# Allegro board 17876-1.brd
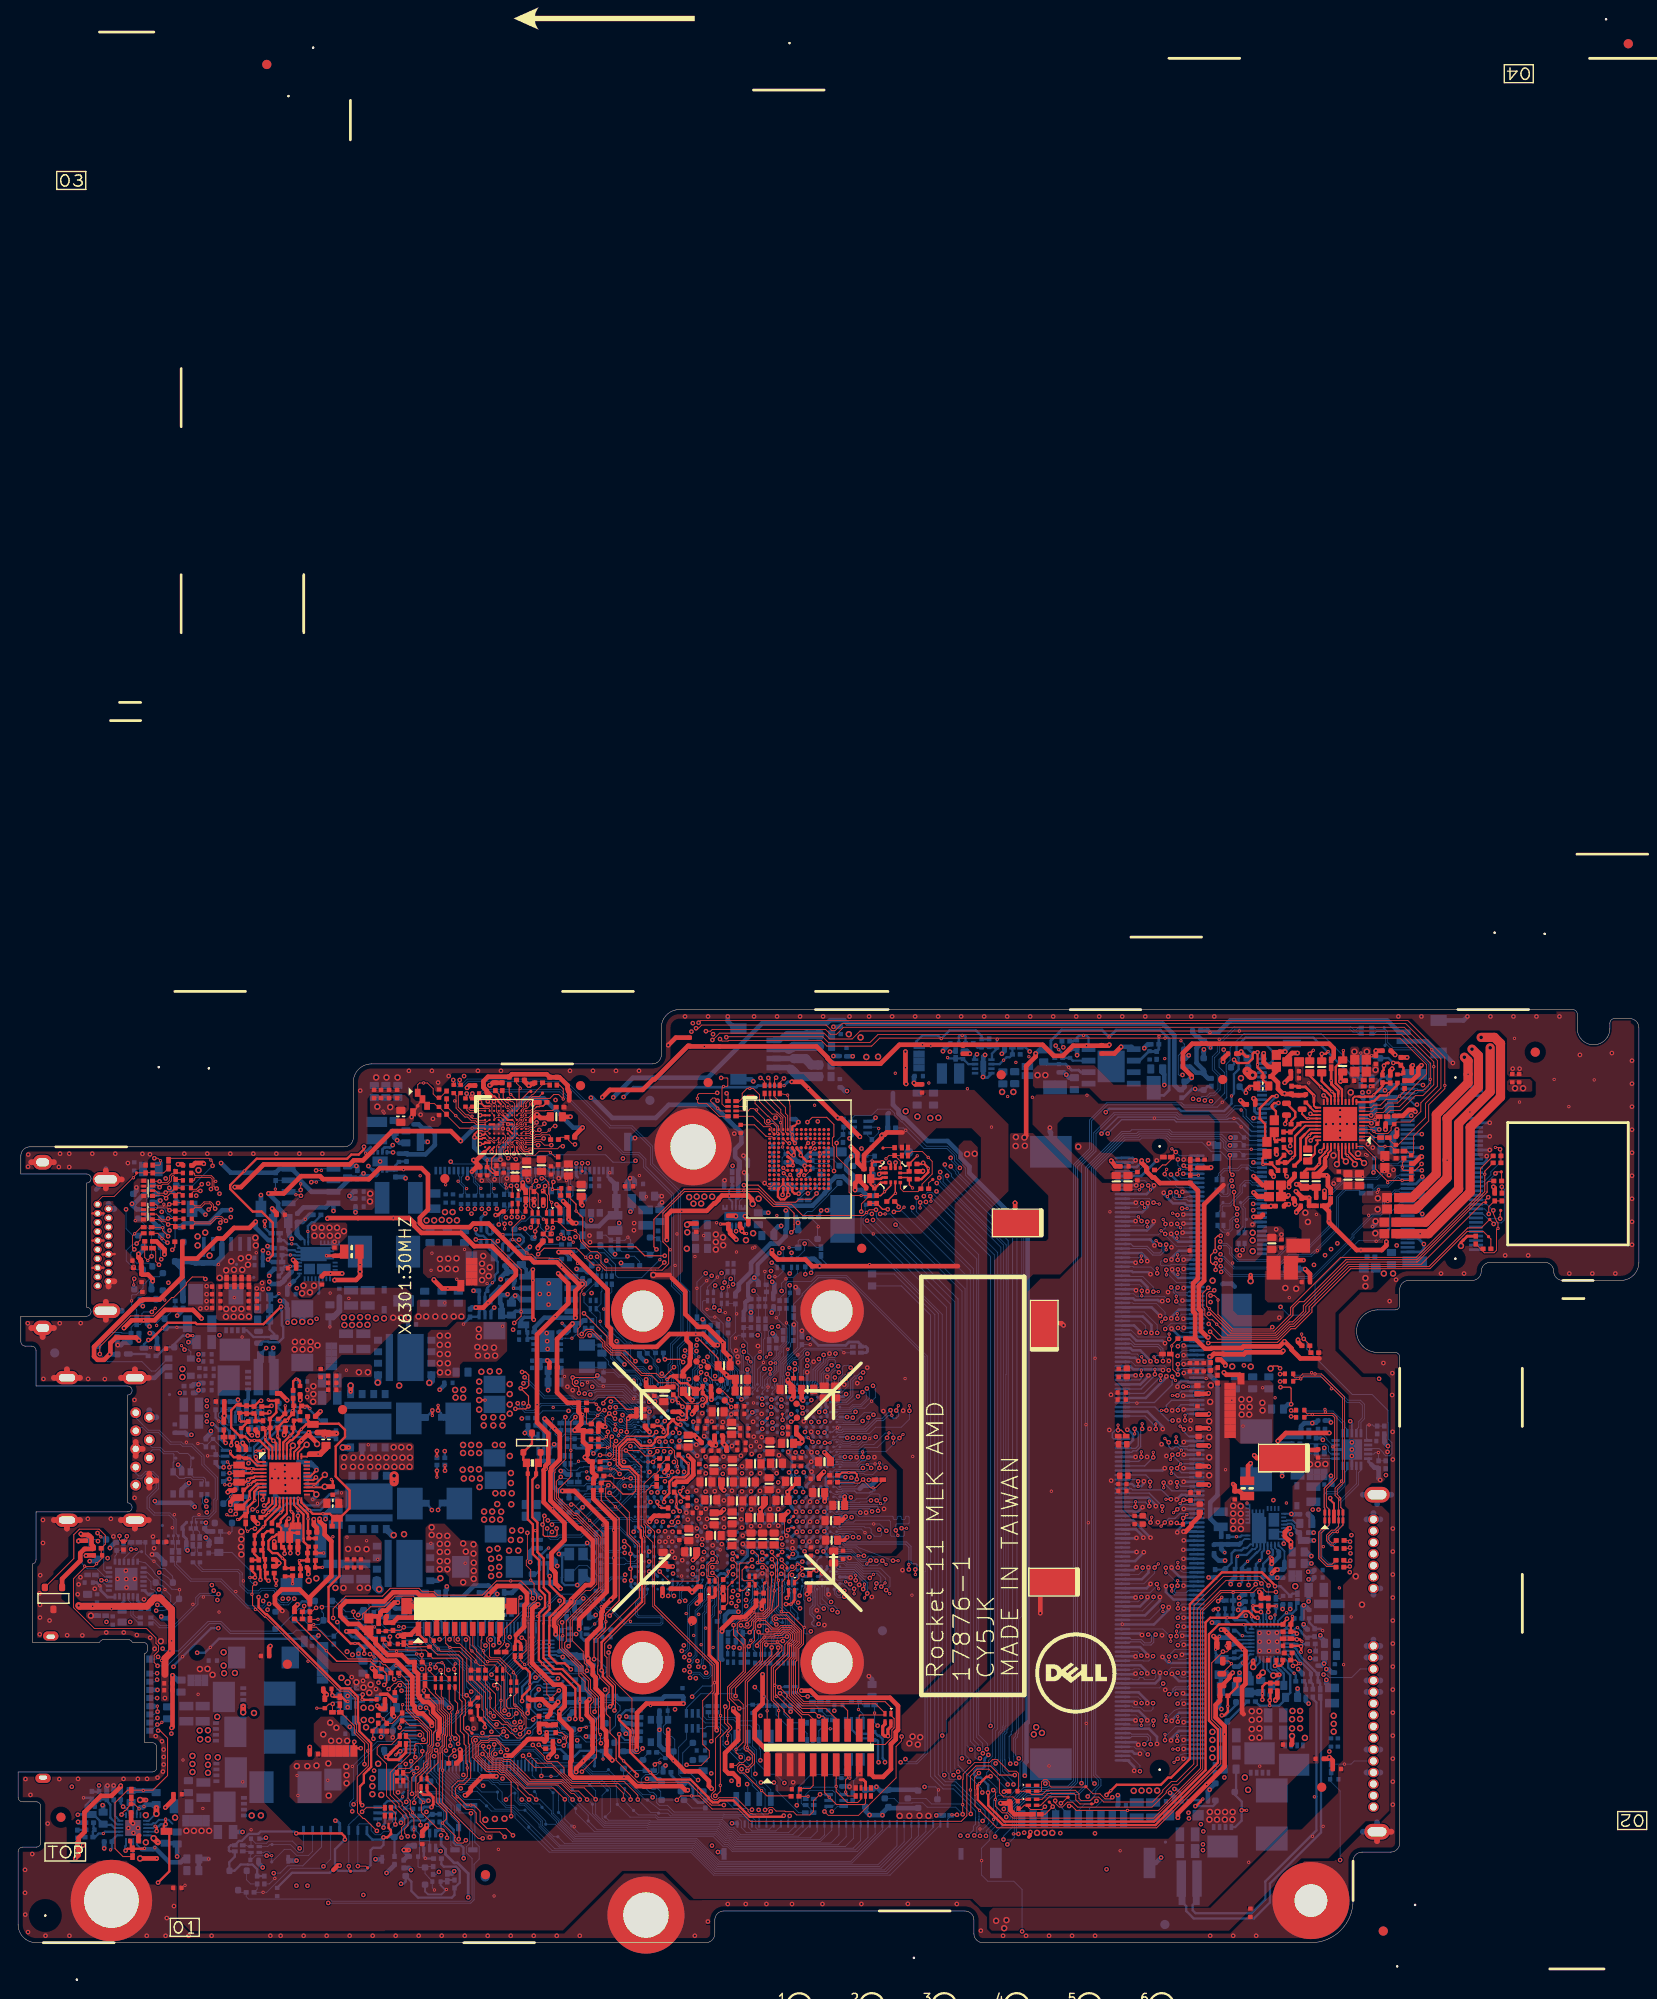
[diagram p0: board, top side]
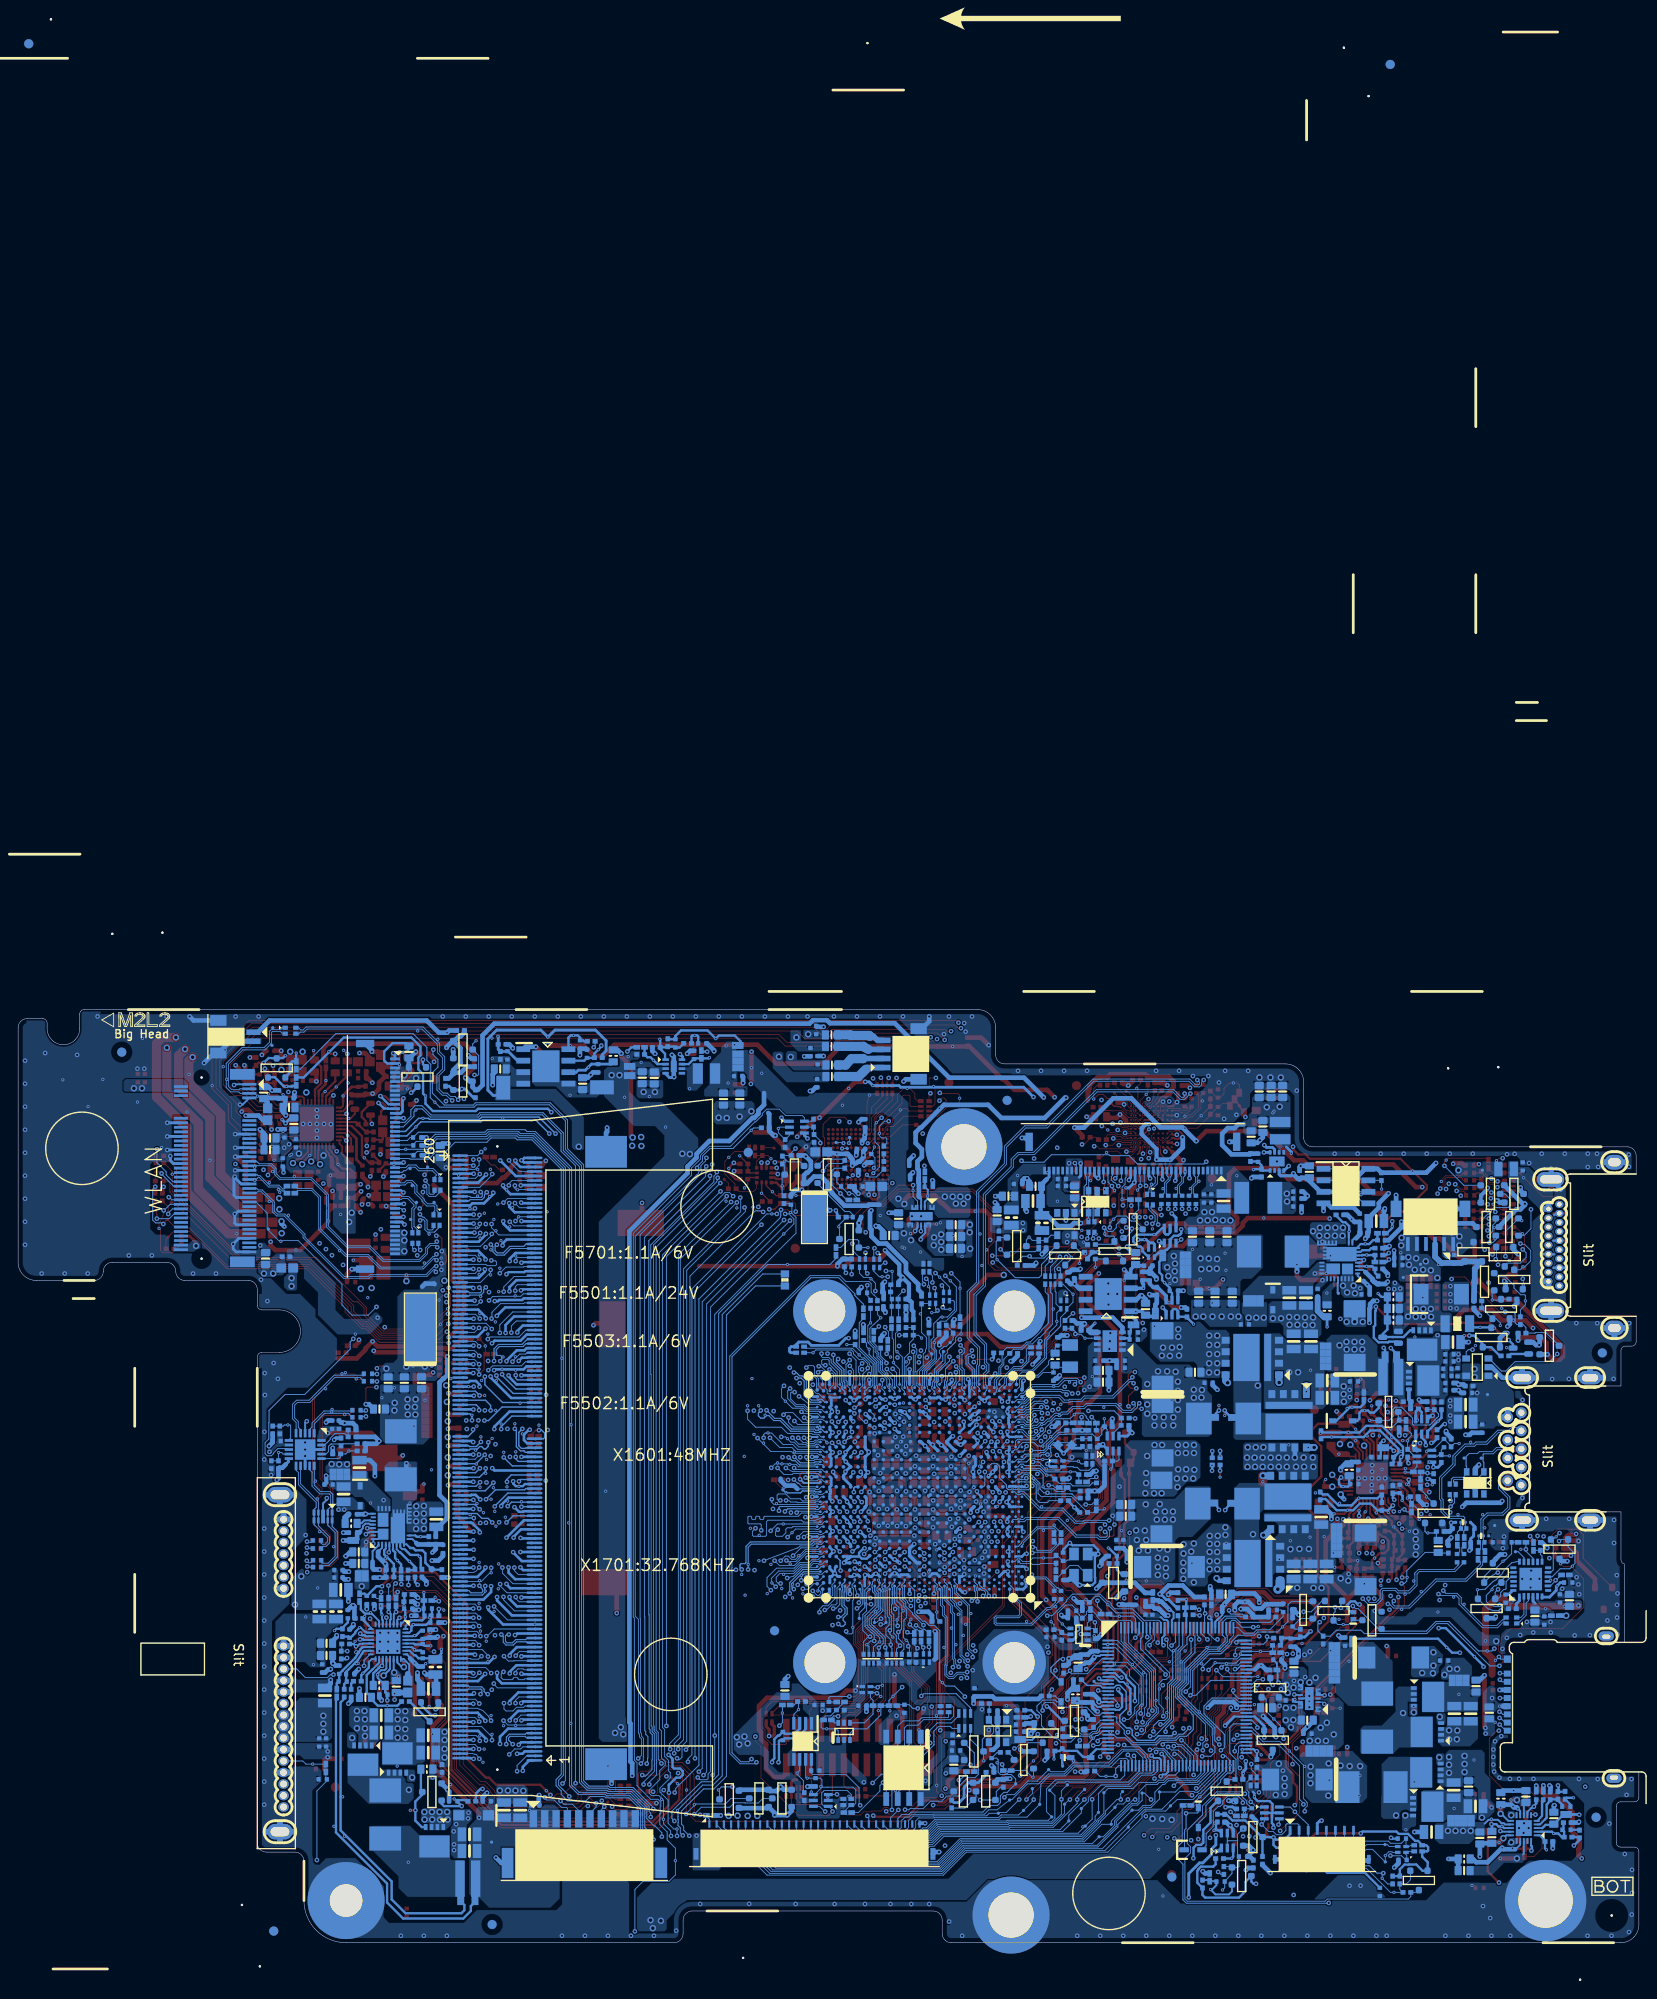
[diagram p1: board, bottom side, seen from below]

Outline 178.9 x 103 mm; copper layers: TOP, L2VCC, L3, L4, L5GND, BOTTOM. Coordinates in mm from the lower left corner of the outline.
Outline path: 0,18.85 0,16.05 arc(0.15,15.7) 0.5,15.55 2,15.55 arc(2.35,15.4) 2.5,15.05 2.5,11.05 arc(2.35,10.7) 2,10.55 0.5,10.55 arc(0.15,10.4) 0,10.05 0,2 arc(0.59,0.59) 2,0 75.9,0 arc(76.61,0.29) 76.9,1 76.9,2.5 arc(77.19,3.21) 77.9,3.5 104.5,3.5 arc(105.21,3.21) 105.5,2.5 105.5,1 arc(105.79,0.29) 106.5,0 142.7,0 arc(145.99,1.36) 147.35,4.65 147.35,9 arc(147.64,9.71) 148.35,10 151.5,10 arc(152.21,10.29) 152.5,11 152.5,64.65 arc(152.35,65) 152,65.15 150.09,65.15 arc(147.74,67.5) 150.09,69.85 152,69.85 arc(152.35,70) 152.5,70.35 152.5,72.1 arc(152.79,72.81) 153.5,73.1 160.5,73.1 arc(161.21,73.39) 161.5,74.1 arc(161.79,74.81) 162.5,75.1 168.5,75.1 arc(169.21,74.81) 169.5,74.1 arc(169.79,73.39) 170.5,73.1 176.9,73.1 arc(178.31,73.69) 178.9,75.1 178.9,101 arc(178.61,101.71) 177.9,102 176.2,102 arc(175.85,101.85) 175.7,101.5 175.7,100.9 arc(173.9,99.1) 172.1,100.9 172.1,102.5 arc(171.95,102.85) 171.6,103 73,103 arc(71.59,102.41) 71,101 71,98 arc(70.71,97.29) 70,97 39,97 arc(37.59,96.41) 37,95 37,88.85 arc(36.71,88.14) 36,87.85 1.3,87.85 arc(0.59,87.56) 0.3,86.85 0.3,84.85 7.55,84.85 arc(8.05,84.35) 7.55,83.85 7.55,70.15 arc(8.05,69.65) 7.55,69.15 0.3,69.15 0.3,66.35 arc(0.45,66) 0.8,65.85 1.48,65.85 arc(1.83,65.7) 1.98,65.35 1.98,61.45 12.08,61.45 arc(12.58,60.95) 12.08,60.45 12.08,48.55 arc(12.58,48.05) 12.08,47.55 1.98,47.55 1.98,42.29 arc(1.87,41.98) 1.6,41.8 1.6,33.15 8.99,33.15 arc(9.18,33.37) 9.45,33.46 12.15,33.46 arc(12.42,33.37) 12.61,33.15 13.8,33.15 arc(14.15,33.01) 14.3,32.66 14.3,32.38 arc(14.2,32.08) 13.95,31.9 13.95,22.07 14.8,22.07 arc(15.15,21.93) 15.3,21.58 15.3,19.34 arc(15.15,18.99) 14.8,18.85 0,18.85

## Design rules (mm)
constraint set DEFAULT: min track width 0.127
net group 3V_5V_10MIL: nets PWR_3D3V_FB PWR_5V_FB
net group APU_SVC: nets APU_SVC SVID_CLK_CPU
net group APU_SVD: nets APU_SVD SVID_DATA_CPU
net group APU_SVT: nets APU_SVT SVID_ALERT#_CPU
net group AUDIO_DIGITAL_50_MW_TP: nets HDA_CODEC_SDIN1_R HDA_CODEC_SDIN2_R
net group BT_USB20_CON_N5: nets BT_USB20_CON_N5 BT_USB20_N5
net group BT_USB20_CON_P5: nets BT_USB20_CON_P5 BT_USB20_P5
net group CARD1_USB20_CON_N2: nets CARD1_USB20_CON_N2 CARD1_USB20_N2
net group CCD_USB20_CON_N0: nets CCD_USB20_CON_N0 CCD_USB20_N0
net group CORE_SENSE-DIFF1: nets VCCCORE_SENSE VSSCORE_SENSE
net group DDR4_CHA_CMD_55OHM: nets M_A_EVENT# M_A_EVENT#_APU
net group EDP_AUX_CON_N: nets EDP_AUX_CON_N EDP_AUX_CPU_N
net group EDP_AUX_CON_P: nets EDP_AUX_CON_P EDP_AUX_CPU_P
net group EDP_TX_CON_N0: nets EDP_TX_CON_N0 EDP_TX_CPU_N0
net group EDP_TX_CON_N1: nets EDP_TX_CON_N1 EDP_TX_CPU_N1
net group EDP_TX_CON_P0: nets EDP_TX_CON_P0 EDP_TX_CPU_P0
net group EDP_TX_CON_P1: nets EDP_TX_CON_P1 EDP_TX_CPU_P1
net group EMMC_SATA_RX_N1: nets EMMC_SATA_RX_N1 EMMC_SATA_RX_N1_C
net group EMMC_SATA_RX_P1: nets EMMC_SATA_RX_P1 EMMC_SATA_RX_P1_C
net group EMMC_SATA_TX_N1: nets EMMC_SATA_TX_N1 EMMC_SATA_TX_N1_C
net group EMMC_SATA_TX_P1: nets EMMC_SATA_TX_P1 EMMC_SATA_TX_P1_C
net group FAN_TACH: nets FAN_TACH1 FAN_TACH1_C
net group HDA_BITCLK_CODEC: nets HDA_BITCLK_CODEC HDA_BITCLK_CODEC_R
net group HDD_SATA_RX_CON_N0: nets HDD_SATA_RX_RE_N1 SATA3_PRX_DTX_N0_L
net group HDD_SATA_RX_CON_P0: nets HDD_SATA_RX_RE_P1 SATA3_PRX_DTX_P0_L
net group HDMI_DDI_TX_CON_N0: nets HDMI_DDI_TX_CON_N0 HDMI_DDI_TX_N0
net group HDMI_DDI_TX_CON_N3: nets HDMI_DDI_TX_CON_N3 HDMI_DDI_TX_N3
net group HDMI_DDI_TX_CON_P0: nets HDMI_DDI_TX_CON_P0 HDMI_DDI_TX_P0
net group HDMI_DDI_TX_CON_P3: nets HDMI_DDI_TX_CON_P3 HDMI_DDI_TX_P3
net group I2C_TP: nets SENSOR_I2C_SCL SENSOR_I2C_SDA
net group M_A_CLK-DIFF0: nets M_A_CLK0 M_A_CLK#0
net group M_A_CLK-DIFF1: nets M_A_CLK1 M_A_CLK#1
net group M_A_DQS-DIFF0: nets M_A_DQS_DN0 M_A_DQS_DP0
net group M_A_DQS-DIFF1: nets M_A_DQS_DN1 M_A_DQS_DP1
net group M_A_DQS-DIFF2: nets M_A_DQS_DN2 M_A_DQS_DP2
net group M_A_DQS-DIFF3: nets M_A_DQS_DN3 M_A_DQS_DP3
net group M_A_DQS-DIFF4: nets M_A_DQS_DN4 M_A_DQS_DP4
net group M_A_DQS-DIFF5: nets M_A_DQS_DN5 M_A_DQS_DP5
net group M_A_DQS-DIFF6: nets M_A_DQS_DN6 M_A_DQS_DP6
net group M_A_DQS-DIFF7: nets M_A_DQS_DN7 M_A_DQS_DP7
net group NB_SENSE-DIFF1: nets VDDNB_SENSE VSSNB_SENSE
net group OTHER_6: nets RSTN S5_ENABLE
net group POWER_12_TP: nets CARD_AV18 CARD_RREF
net group POWER_15M: nets PWR_0D775V PWR_0D775V_VREF
net group POWER_20_TP: nets AD+_G_2 Q2506_S
net group POWER_20M_10M: nets CPVDD PWR_CHG_CMSRC
net group POWER_40M_25M: nets PWR_CORE_LG1 PWR_VDDNB_LG
net group POWER_100: nets EMMC_VCC PWR_VDDQ_VTTREF
net group POWER_VDDQ_280M: nets PWR_VDDQ_VCC VTT_CT_0.95V
net group PSID_4M: nets PS_ID PSID_EC
net group PWR_VDDNB_CORE_5M: nets PWR_CORE_HG1 PWR_VDDNB_HG
net group SD_MMC_CLK/MS_DATA2: nets SD_MMC_CLK/MS_DATA2 SP5
net group SENSE_CHG_PG-DIFF1: nets PG_1 PG_2
net group SENSE_CHG_SRPN-DIFF1: nets PWR_CHG_SRN PWR_CHG_SRP
net group SIGNAL_V_F_50_OHM: nets BP_D BP_G
net group T8: nets VD_IN1 VD_IN1_C
net group THERM_10MIL: nets VD1_EN# VD_OUT1#
net group THERMAL-DIFF: nets P2800_DXN P2800_DXP
net group USB1_USB30_TX_CMC_N2: nets USB1_USB30_TX_CMC_N2 USB1_USB30_TX_N2
net group USB1_USB30_TX_CMC_P2: nets USB1_USB30_TX_CMC_P2 USB1_USB30_TX_P2
net group USB3_RX_CON-DIFF1: nets USB1_USB30_RX_CON_N2 USB1_USB30_RX_CON_P2
net group USB3_RX_CPU-DIFF1: nets USB1_USB30_RX_N2 USB1_USB30_RX_P2
net group USB3_TX_CON-DIFF1: nets USB1_USB30_TX_CON_N2 USB1_USB30_TX_CON_P2
net group WLAN_CLK_CPU_N3: nets WLAN_CLK_CPU_N3 WLAN_CLK_CPU_N3_R
net group WLAN_CLK_CPU_P3: nets WLAN_CLK_CPU_P3 WLAN_CLK_CPU_P3_R
net group WLAN_PCIE_TX_CON_N3: nets WLAN_PCIE_TX_CON_N3 WLAN_PCIE_TX_N3
net group WLAN_PCIE_TX_CON_P3: nets WLAN_PCIE_TX_CON_P3 WLAN_PCIE_TX_P3
net group WLANTX_N3: nets WLAN_PCIE_RX_N3 WLANTX_N3
net group WLANTX_P3: nets WLAN_PCIE_RX_P3 WLANTX_P3
net group XTL_48M_TP: nets 48M_X2 R1930.R
net group 3V_5V_10MIL_TP: nets PWR_5V_FB_A
net group 3V_5V_20MIL: nets PWR_3D3V_BOOT PWR_3D3V_BOOT_A PWR_5V_BOOT PWR_5V_BOOT_A
net group APU_SPI_CLK: nets APU_SPI_CLK SPI_CLK_KBC SPI_CLK_ROM
net group APU_SPI_CS1#: nets SPI_CS_ROM_N0
net group APU_SPI_HOLD#: nets SPI_HOLD_CPU
net group APU_SPI_SI_R: nets APU_SPI_SI_R SPI_SI_KBC SPI_SI_ROM
net group APU_SPI_SO_R: nets SPI_SO_CPU
net group APU_SPI_WP#: nets SPI_WP_CPU
net group BKLT_EDP-MW: nets BKLT_CTRL EC_BRIGHTNESS L_BKLT_CTRL L_BKLT_CTRL_B L_BKLT_CTRL_CPU LCD_BRIGHTNESS LVDS_VDD_EN LVDS_VDD_EN_B LVDS_VDD_EN_CPU LVDS_VDD_EN_R
net group CCD_USB20_CON_P0: nets CCD_USB20_CON_P0
net group CLK_FST_SPI-MW: nets SPI_SCK
net group CPU_SIDE-MW: nets AD_IA DBC_EN DBC_EN_R ECSMI#_KBC EDP_HPD_CPU FALL_INT2 FFS_INT2 FFS_INT2_Q FFS_INT2_Q_R HDMI_DET_CPU HDMI_HPD_B HDMI_HPD_E HDMI_HPD_G HPD_HDMI_CON INT_TP# INT_TP#_CONN PLT_RST# PM_PWRBTN# PROCHOT#_EC PROJECT_ID1 RSMRST#_KBC RTC_CLK WLAN_CLKREQ_CPU_N3
net group CPU_SIDE_PROCHOT: nets H_PROCHOT#
net group DDR4_CHA_CMD-MW: nets DDR4_A_DRAMRST# M_A_A0 M_A_A1 M_A_A2 M_A_A3 M_A_A4 M_A_A5 M_A_A6 M_A_A7 M_A_A8 M_A_A9 M_A_A10 M_A_A11 M_A_A12 M_A_A13 M_A_ACT# M_A_ALERT_N M_A_BA0 M_A_BA1 M_A_BG0 M_A_BG1 M_A_CAS# M_A_PARITY M_A_RAS# M_A_WE# M_VREFDQ
net group DDR4_CHA_CTRL-MW: nets M_A_CKE0 M_A_CKE1 M_A_CS#0 M_A_CS#1 M_A_ODT0 M_A_ODT1
net group DDR4_CHA_DATA-MW: nets M_A_DM0 M_A_DM1 M_A_DM2 M_A_DM3 M_A_DM5 M_A_DM6 M_A_DM7 M_A_DQ0 M_A_DQ1 M_A_DQ2 M_A_DQ3 M_A_DQ4 M_A_DQ6 M_A_DQ7 M_A_DQ8 M_A_DQ9 M_A_DQ10 M_A_DQ11 M_A_DQ12 M_A_DQ13 M_A_DQ14 M_A_DQ15 M_A_DQ16 M_A_DQ17 M_A_DQ18 M_A_DQ19 M_A_DQ20 M_A_DQ21 M_A_DQ22 M_A_DQ23 M_A_DQ24 M_A_DQ25 M_A_DQ26 M_A_DQ28 M_A_DQ29 M_A_DQ34 M_A_DQ35 M_A_DQ38 M_A_DQ39 M_A_DQ40 M_A_DQ41 M_A_DQ42 M_A_DQ43 M_A_DQ44 M_A_DQ45 M_A_DQ46 M_A_DQ47 M_A_DQ48 M_A_DQ49 M_A_DQ50 M_A_DQ51 M_A_DQ52 M_A_DQ53 M_A_DQ54 M_A_DQ55 M_A_DQ56 M_A_DQ57 M_A_DQ58 M_A_DQ59 M_A_DQ60 M_A_DQ61 M_A_DQ62 M_A_DQ63
net group DDR4_CHA_DATA_10M: nets M_A_DM4 M_A_DQ27 M_A_DQ30 M_A_DQ31 M_A_DQ32 M_A_DQ33 M_A_DQ36 M_A_DQ37
net group DDR4_CHA_DATA_MW_TP: nets M_A_DQ5
net group EMMC_S10: nets EMMC_E9 EMMC_E10 EMMC_F10 EMMC_K10 EMMC_RESET# EMMC_VCC1N EMMC_VCC2N
net group EMMC_S10_TP: nets EMMC_VDDI
net group GND_20: nets MIC_GND
net group GND_100: nets AUD_AGND
net group HDA_CODEC_SDIN0_R: nets HDA_SDIN0_CPU
net group HDA_CODEC_SDOUT_R: nets HDA_SDOUT_CODEC
net group HDA_CODEC_SYNC_R: nets HDA_SYNC_CODEC
net group HDMI_DDI_TX_CON_N1: nets HDMI_DDI_TX_N1
net group HDMI_DDI_TX_CON_N2: nets HDMI_DDI_TX_N2
net group HDMI_DDI_TX_CON_P1: nets HDMI_DDI_TX_P1
net group HDMI_DDI_TX_CON_P2: nets HDMI_DDI_TX_P2
net group I2C: nets I2C1_1V8_CLK I2C1_1V8_DATA SENSOR_I2C_SCL_R SENSOR_I2C_SDA_R TP_CLK TP_DAT TP_I2C_CLK TP_I2C_DATA
net group KB: nets KCOL0 KCOL1 KCOL2 KCOL3 KCOL4 KCOL5 KCOL6 KCOL7 KCOL8 KCOL9 KCOL10 KCOL11 KCOL12 KCOL13 KCOL14 KCOL15 KCOL16 KROW0 KROW1 KROW2 KROW3 KROW4 KROW5 KROW6 KROW7
net group LPC-MW: nets APU_LPC_PD# APU_LPC_PME# APU_LPC_SMI# INT_SERIRQ
net group M_ZVDDIO: nets M_ZVDDIO P_ZVDDP P_ZVSS SATA_ZVSS
net group OTHER_4: nets 1D8V_AUX_EN 1D8V_S0_EN 1D8V_S0_EN_R 1D8V_SPI_EN# 3V_5V_EN 3V_S0_EN 5V_DDC_HDMI1 5V_DDC_HDMI2 AC_PRES_KBC AC_PRES_R AGPIO3 AGPIO11 AGPIO92 AGPIO130 ALERT# APU_ALERT# APU_DBRDY APU_DBREQ# APU_DEVSLP1 APU_FANIN APU_FANOUT APU_LDRQ0# APU_PWRBTN#_R APU_PWROK APU_PWROK_HDT APU_RSMRST# APU_RSMRST#_R APU_RST# APU_RST#_R APU_RST_L_BUF APU_S0A3_IND APU_SIC APU_SID APU_SLP_S3# APU_SLP_S5# APU_TCK APU_TDI APU_TDO APU_TEST0 APU_TEST1 APU_TEST2 APU_TEST6 APU_TEST9 APU_TEST10 APU_TEST14_BP1 APU_TEST15_BP3 APU_TEST16_BP5 APU_TEST17_BP7 APU_TEST18_HDT20 APU_TEST19_HDT18 APU_TEST28_H APU_TEST28_L APU_TEST31 APU_TEST36 APU_TEST41 APU_THERMDA APU_THERMDC APU_TMS APU_TRST# APU_TRST#_R APU_VSS_SENSE_A BAT_IN# BLON_OUT BLUETOOTH_EN BLUETOOTH_EN_R CAP_LED CAP_LED# CAP_LED_R# CLK_REQG CR_GPIO0 DBRDY1 DBRDY2 DBRDY3 DP_2K_ZVSS DP_150_ZVSS DP_HPD0_C DVSS E51_RX1 E51_RX2 E51_TX1 E51_TXD EC_MUTE# ECRST# ECSCI#_KBC EDP_BLON EGPIO95 EGPIO96 EGPIO99 EGPIO100 FAN_PWM1_C GPIO1 GPIO2 GPIO3 GPIO67 GROUPB_PWRGD H_A20GATE HALL_KB_DIS# HDD_DEVSLP HDD_DEW1 HDD_DEW2 HDMI_IN# HVBEN_L INT_SERIRQ_OE INT_TP#_R KB_LOOP KBC_BEEP KBC_ON#_GATE KBC_ON#_GATE_L KBC_PECI KBC_PWRBTN# KBRST# LCD_TST LCD_TST_EN LCD_TST_KBC LID_CLOSE# LVDS_VDD_EN_KBC MODEL_ID MODEL_ID_AD NC#7 PBAT_PRES1# PCB_VER_AD PCIE_RST#_C PDB_R PLTRST#_CPU_D PQ3802_1 PQ4405_2 PQ4405_3 PQ4405_5 PQ4405_6 PQ4408_C PQ4408_E PQ4415_C PSID_DISABLE#_R_C PSL_IN2# PSL_OUT# PURE_HW_SHUTDOWN# PWR_3D3V_EN Q1702_2 Q2406_D Q2406_G RTC_DET# RUNPWROK_D S5_MUX_APU SATA3_DE1_HDD SATA3_DE2_HDD SD_CD# SD_WP#/MS_DATA1_C SENSOR_KB_DIS SER_RXD SER_TXD SVID_PWRGD SVID_PWRGD_R SYS_PRES1# SYS_PWRGD SYS_PWRGD_G SYS_PWRGD_R SYS_RESET# T_CRIT# THERM_SYS_SHDN# TOUCH_PANEL_EN TP_DISABLE# TP_DISABLE#_R TP_ON# TP_ON#_GATE UART_RX UART_TX USB2_PWR_EN# USB3_PWR_EN# USB_OC#0 USB_OC#1 VOL_DOWN# VOL_UP# WAKE_L WIFI_RF_EN WIFI_RF_EN_R
net group OTHER_4_TP: nets 1D8V_S0_EN_D APU_KBRST# BLON_OUT_C CAP_LED_Q GPIO0 GPIO4 GPIO5 GROUPB_PWRGD_R LCD_TST_C PSL_IN1# Q5102_G RTCRST_ON SATA3_EQ1_HDD SATA3_EQ2_HDD SD_CD#_CARD
net group OTHER_5: nets ACLIM TOUCH_PANEL_INTR# TPNL_INT
net group OTHER_6_TP: nets SD1_REXT
net group OTHER_12: nets LDO1_CAP LDO2_CAP LDO3_CAP V3D3_STB
net group OTHER_12_TP: nets CPVEE
net group P27_AUDIO_ANALOG: nets AUD_HP1_JACK_R AUD_HP1_JACK_R1 AUD_PC_BEEP AUD_PC_BEEP_C AUD_PORTA_L_R_B AUD_PORTA_R_R_B AUD_SENSE AUD_SENSE_A CBN HDA_SPKR_R JACK_PLUG KBC_BEEP_R LINE1-L_C LINE1-L_R LINE1_L LINE1_R LINE1_VREFO SPKR
net group P27_AUDIO_ANALOG_TP: nets AUD_HP1_JACK_L AUD_HP1_JACK_L1 AUD_VREF CBP LINE1_VREFO_D1 LINE1_VREFO_D2
net group POWER_4M: nets DM1_SA0 DM1_SA1 DM1_SA2
net group POWER_8: nets Q6204_S
net group POWER_10: nets 3D3V_GSEN2 3V5V_CT2 5V_AUX_S5 ACOK_IN I_BATT MIC_CAP PD4410_2 PQ4209_D PWR_1D8V_FB PWR_CHG_ACDET PWR_CHG_ACN PWR_CHG_ACOK PWR_CHG_ACP PWR_CHG_REGN PWR_CHG_SCL PWR_CHG_SDA PWR_CPU_ISEN1 Q6205_D Q6206_D RTC_1D5V_PWR RTC_1D5V_S5 SATA_ZVDD_095 USB_SS_ZVDD_095 USB_SS_ZVSS USB_ZVSS VDD VDDIO_AUDIO
net group POWER_10_TP: nets 3V5V_CT1
net group POWER_10_VIA: nets DC_IN_D
net group POWER_10_VIA_TP: nets AD+_G_1
net group POWER_10M_10M: nets 1D8V_S5_PWRGD 5V_S0_EN AC_DIS_R CCLIM PR_2 PWR_1D0V_FB PWR_CHG_AD_OFF_R VCORE_PWRGD
net group POWER_10M_POWER: nets 0D95V_S0_EN 0D95V_S5_EN 0D95V_S5_PWRGD 3V_5V_PWRGD 3V_5V_PWRGD_R AD+_R AD_OFF_L AD_OFF_R PWR_0D95V_CS PWR_0D95V_EN PWR_0D95V_FB PWR_0D95V_PG PWR_0D775V_EN PWR_0D775V_EN_R PWR_1D8V_EN PWR_1D8V_FB_R1 PWR_1D8V_FB_R2 PWR_1D8V_PG PWR_2D5V_PWRGD PWR_3D3V_FB_A PWR_3D3V_FB_B PWR_5V_EN PWR_5V_VO PWR_5V_VREG PWR_CHG_AD_OFF PWR_CHG_AMON PWR_CHG_ASGATE PWR_CHG_BATGONE PWR_CHG_BMON PWR_CHG_COMP PWR_CHG_FSET PWR_CHG_NTC PWR_CHG_SRN_R PWR_CHG_SRP_R PWR_CORE_COMP PWR_CORE_COMP_A PWR_CORE_COMP_B PWR_CORE_EN PWR_CORE_FB_A PWR_CORE_FB_R PWR_CORE_IMON PWR_CORE_ISEN1_N PWR_CORE_ISEN1_P PWR_CORE_ISEN_N PWR_CORE_ISEN_P PWR_CORE_ISUMN PWR_CORE_ISUMP PWR_CORE_NTC PWR_CORE_NTC_A_R PWR_CORE_PGOOD PWR_CORE_SVC PWR_CORE_SVD PWR_CORE_SVT PWR_CORE_VDD PWR_CORE_VDDIO PWR_CORE_VSEN1_N PWR_CORE_VSEN1_P PWR_OPCN PWR_OPCP PWR_VBAT PWR_VDDNB_COMP PWR_VDDNB_FB PWR_VDDNB_FB_A PWR_VDDNB_FB_B PWR_VDDNB_FB_C PWR_VDDNB_ISEN1_N PWR_VDDNB_ISEN1_N_A PWR_VDDNB_ISEN1_P PWR_VDDNB_ISEN1_P_A PWR_VDDNB_ISUMN PWR_VDDNB_ISUMN_A PWR_VDDNB_NTC PWR_VDDNB_NTC_A PWR_VDDNB_PG PWR_VDDNB_VSEN PWR_VDDNBE_IMON PWR_VDDQ_CS PWR_VDDQ_EN PWR_VDDQ_FB PWR_VDDQ_TON PWR_VPP_EN1 PWR_VTT_EN VDDQ_PWRGD
net group POWER_10M_POWER_TP: nets 0D775V_S5 PWR_0D95V_TON PWR_3D3V_CS PWR_3D3V_VREG PWR_5V_CS PWR_CHG_DCIN PWR_CHG_DCIN_R PWR_CHG_NTC_1 PWR_CHG_PROG PWR_CORE_VR_HOT#
net group POWER_12: nets PWR_VPP_FB PWR_VPP_VCNTL SDREG
net group POWER_15M_TP: nets PWR_0D775V_VIN
net group POWER_20: nets 1D8V_DVDD-IO +3V_1D8V_AVDD +RTC_PWR DDR_VREF_S3 EC_AVCC EC_VCC1V8 KBC_VCORF PD4403_A PD4403_K PWR_0D95V_SNUB PWR_CHG_BATDRV PWR_VDDQ_SNUB Q6203_S RTC_AUX_S5 RTC_DET#_G TPAN_VDD VBKUP VTT_CT_1.8V
net group POWER_25M: nets VDDCR_FCH_EN
net group POWER_25M_20M: nets PWR_0D95V_BOOT_A PWR_VDDNB_BOOT PWR_VDDNB_BOOT_A
net group POWER_25M_20M_TP: nets PWR_CHG_BTST PWR_CHG_BTST1 PWR_VDDQ_BOOT PWR_VDDQ_BOOT_A
net group POWER_40: nets SD1_POWER
net group POWER_40M_10M: nets PWR_0D95V_VCC PWR_0D95V_VDDQ PWR_0D95V_VLDOIN PWR_0D95V_VTTREF
net group POWER_240M_10M: nets PWR_VDDQ_VDDQ
net group POWER_VDDQ_280M_TP: nets PWR_VDDQ_LVOIN
net group PSID_25MIL: nets PS_ID_R
net group SD_DATA_CMD: nets SD_MMC_CMM/MS_DATA3 SD_MMC_DAT1 SD_MMC_DATA0/MS_DATA5 SD_MMC_DATA2/MS_BS SD_MMC_DATA3/MS_CLK
net group SENSOR: nets GSEN2_INT1 GSEN2_INT1_R GSEN2_INT2 GSEN2_INT2_R GSENSOR_CS GSENSOR_SDO
net group SMBUS_DAT-MW: nets BAT_SCL BAT_SDA DMIC_CLK DMIC_CLK_C DMIC_DATA DMIC_DATA_C DMIC_DATA_R NCT_DATA NCT_DATA_R PBAT_SMBCLK1 PBAT_SMBDAT1 SMB0_CLK SMB0_DATA SML1_CLK SML1_DATA TP_CLK_C TP_DATA_C TPCLK TPDATA
net group SMBUS_DAT_MW_TP: nets DMIC_CLK_R NCT_CLK NCT_CLK_R
net group SPI_VIA_12MIL: nets APU_SPI_CS2# APU_SPI_TPM_CS# SPI_CSN SPI_MISO SPI_MOSI
net group SPK11_40M: nets AUD_SPK_L+_C11 AUD_SPK_L-_C11 AUD_SPK_R+_C11 AUD_SPK_R-_C11
net group USB1_USB20_CON_N6: nets USB1_USB20_N6
net group USB1_USB20_CON_P6: nets USB1_USB20_P6
net group USB3_USB20_CON_N4: nets USB3_USB20_CON_N4
net group USB3_USB20_CON_P4: nets USB3_USB20_CON_P4
net group XTL_32D768K_VIA15: nets 25M_48M_OSC X25M_48M_OSC XI XO XO_R XTL_32K_X1_CPU XTL_32K_X2_CPU
net group XTL_48M: nets 48M_X1

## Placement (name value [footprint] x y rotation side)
AFTP2901  AFTE14P-GP  [AFTE14P-75]  86.97 100.14 270 bottom
AFTP2902  AFTE14P-GP  [AFTE14P-75]  85.53 98.87 270 bottom
AFTP2903  AFTE14P-GP  [AFTE14P-75]  86.94 97.57 270 bottom
AFTP2904  AFTE14P-GP  [AFTE14P-75]  85.65 96.09 270 bottom
AFTP2906  AFTE14P-GP  [AFTE14P-75]  138.4 92.31 180 top
AFTP2907  AFTE14P-GP  [AFTE14P-75]  137.06 90.96 0 top
AFTP2908  AFTE14P-GP  [AFTE14P-75]  135.74 97.82 0 top
AFTP2909  AFTE14P-GP  [AFTE14P-75]  151.23 97.11 270 top
AFTP3401  AFTE14P-GP  [AFTE14P-75]  16.71 60.5 90 bottom
AFTP3402  AFTE14P-GP  [AFTE14P-75]  19.29 53.49 270 bottom
AFTP3403  AFTE14P-GP  [AFTE14P-75]  17.4 53.49 270 bottom
AFTP3404  AFTE14P-GP  [AFTE14P-75]  15.92 46.05 90 bottom
AFTP4301  AFTE14P-GP  [AFTE14P-75]  115.9 16.05 270 top
AFTP4302  AFTE14P-GP  [AFTE14P-75]  118.49 15.32 270 top
AFTP4303  AFTE14P-GP  [AFTE14P-75]  117.86 17.22 270 top
AFTP4304  AFTE14P-GP  [AFTE14P-75]  126.64 11.1 180 bottom
AFTP4305  AFTE14P-GP  [AFTE14P-75]  111.56 11.66 0 top
AFTP4306  AFTE14P-GP  [AFTE14P-75]  113.82 15.52 0 top
AFTP4307  AFTE14P-GP  [AFTE14P-75]  24.1 74.88 180 bottom
AFTP4308  AFTE14P-GP  [AFTE14P-75]  21.78 74.99 180 bottom
AFTP4309  AFTE14P-GP  [AFTE14P-75]  26.01 73.43 180 bottom
AFTP5402  AFTE14P-GP  [AFTE14P-75]  17.27 85.27 180 bottom
AFTP6101  AFTE14P-GP  [AFTE14P-75]  159.51 77.55 270 top
AFTP6102  AFTE14P-GP  [AFTE14P-75]  151.28 78.77 270 bottom
AFTP6104  AFTE14P-GP  [AFTE14P-75]  162.43 79.83 270 top
AFTP6105  AFTE14P-GP  [AFTE14P-75]  161.99 81.71 270 top
AFTP6110  AFTE14P-GP  [AFTE14P-75]  162.31 77.93 270 top
AFTP6111  AFTE14P-GP  [AFTE14P-75]  150.79 100.99 0 bottom
AFTP6113  AFTE14P-GP  [AFTE14P-75]  150.88 99.04 0 bottom
AFTP6501  AFTE14P-GP  [AFTE14P-75]  51.71 15.1 180 bottom
AFTP6502  AFTE14P-GP  [AFTE14P-75]  56.36 12.75 180 bottom
AFTP6503  AFTE14P-GP  [AFTE14P-75]  52.91 16.63 180 bottom
AFTP6504  AFTE14P-GP  [AFTE14P-75]  55.94 14.62 180 bottom
AFTP6505  AFTE14P-GP  [AFTE14P-75]  54.83 16.51 180 bottom
AFTP6506  AFTE14P-GP  [AFTE14P-75]  59.58 11.69 180 bottom
AFTP6507  AFTE14P-GP  [AFTE14P-75]  58.24 13.07 180 bottom
AFTP6508  AFTE14P-GP  [AFTE14P-75]  57.83 14.95 180 bottom
AFTP6509  AFTE14P-GP  [AFTE14P-75]  56.99 16.68 180 bottom
AFTP6510  AFTE14P-GP  [AFTE14P-75]  59.05 16.55 180 bottom
AFTP6511  AFTE14P-GP  [AFTE14P-75]  59.66 14.38 180 bottom
AFTP6512  AFTE14P-GP  [AFTE14P-75]  61.11 12.88 180 bottom
AFTP6513  AFTE14P-GP  [AFTE14P-75]  61.54 14.8 180 bottom
AFTP6514  AFTE14P-GP  [AFTE14P-75]  62.92 13.44 180 bottom
AFTP6515  AFTE14P-GP  [AFTE14P-75]  61.19 16.92 180 bottom
AFTP6516  AFTE14P-GP  [AFTE14P-75]  63.39 15.29 180 bottom
AFTP6517  AFTE14P-GP  [AFTE14P-75]  63.09 17.42 180 bottom
AFTP6518  AFTE14P-GP  [AFTE14P-75]  65.04 16.83 180 bottom
AFTP6520  AFTE14P-GP  [AFTE14P-75]  66.14 15.27 180 bottom
AFTP6521  AFTE14P-GP  [AFTE14P-75]  67.93 14.6 180 bottom
AFTP6522  AFTE14P-GP  [AFTE14P-75]  66.95 17.01 180 bottom
AFTP6523  AFTE14P-GP  [AFTE14P-75]  70.7 14.29 180 bottom
AFTP6524  AFTE14P-GP  [AFTE14P-75]  69.46 15.74 180 bottom
AFTP6525  AFTE14P-GP  [AFTE14P-75]  65.15 19.1 180 bottom
AFTP6526  AFTE14P-GP  [AFTE14P-75]  34.8 8.03 0 top
AFTP6527  AFTE14P-GP  [AFTE14P-75]  64.81 13.88 180 bottom
AFTP6528  AFTE14P-GP  [AFTE14P-75]  41.15 12.02 0 top
AFTP6529  AFTE14P-GP  [AFTE14P-75]  28.02 10.83 180 bottom
AFTP6530  AFTE14P-GP  [AFTE14P-75]  27.99 8.92 180 bottom
AFTP6531  AFTE14P-GP  [AFTE14P-75]  38.58 8.26 0 top
AFTP6532  AFTE14P-GP  [AFTE14P-75]  36.7 7.88 0 top
AFTP6533  AFTE14P-GP  [AFTE14P-75]  68.79 17.53 180 bottom
AFTP6601  AFTE14P-GP  [AFTE14P-75]  96.1 91.58 180 bottom
AFTP6602  AFTE14P-GP  [AFTE14P-75]  132.99 81.71 180 bottom
AFTP6603  AFTE14P-GP  [AFTE14P-75]  135.41 83.57 180 bottom
AFTP6604  AFTE14P-GP  [AFTE14P-75]  135.64 85.45 180 bottom
AFTP6605  AFTE14P-GP  [AFTE14P-75]  133.71 85.6 180 bottom
AFTP6606  AFTE14P-GP  [AFTE14P-75]  134.92 81.71 180 bottom
AFTP6607  AFTE14P-GP  [AFTE14P-75]  135.59 79.84 180 bottom
BATT1  ETY-CON10-33-GP  [3806K-F10N-03L]  116.4 8.8 180 bottom
C303  SCD1U16V2KX-3DLGP  [C402H22]  63.78 38.38 0 bottom
C304  SCD1U16V2KX-3DLGP  [C402H22]  64.54 38.38 0 bottom
C801  SC150P50V2KX-GP  [C402H22]  89.41 26.11 180 bottom
C802  SC150P50V2KX-GP  [C402H22]  81.08 25.81 180 bottom
C803  SCD1U16V2KX-3DLGP  [C402H22]  85.7 26.16 270 bottom
C804  SC150P50V2KX-GP  [C402H22]  85.65 71.73 270 bottom
C1001  SC22U6D3V3MX-1-DL-GP  [C603H40]  80.9 44.56 0 top
C1002  SC22U6D3V3MX-1-DL-GP  [C603H40]  82.18 44.56 0 top
C1003  SC22U6D3V3MX-1-DL-GP  [C603H40]  83.45 44.56 0 top
C1004  SC22U6D3V3MX-1-DL-GP  [C603H40]  81.72 48.78 90 top
C1005  SC22U6D3V3MX-1-DL-GP  [C603H40]  82.9 50.66 180 top
C1006  SC22U6D3V3MX-1-DL-GP  [C603H40]  85.37 50.91 90 top
C1007  SC22U6D3V3MX-1-DL-GP  [C603H40]  78.8 44.51 180 top
C1008  SC1U10V2KX-1GP  [C402H22]  57.67 44 180 bottom
C1009  SC180P50V2JN-1DLGP  [C402H22]  75.34 38.84 180 top
C1010  SC22U6D3V3MX-1-DL-GP  [C603H40]  83.71 52.92 90 top
C1011  SC22U6D3V3MX-1-DL-GP  [C603H40]  74.03 45.04 180 top
C1012  SC22U6D3V3MX-1-GP  [C603H40]  76.83 46.79 180 top
C1013  SC22U6D3V3MX-1-DL-GP  [C603H40]  78.82 46.89 0 top
C1014  SC22U6D3V3MX-1-GP  [C603H40]  79.34 48.77 90 top
C1015  SC22U6D3V3MX-1-DL-GP  [C603H40]  76.94 44.94 90 top
C1016  SC22U6D3V3MX-1-GP  [C603H40]  74.23 43.15 90 top
C1017  SC22U6D3V3MX-1-DL-GP  [C603H40]  78.3 50.85 270 top
C1018  SC22U6D3V3MX-1-DL-GP  [C603H40]  76.46 48.88 270 top
C1019  SC22U6D3V3MX-1-GP  [C603H40]  80.72 50.85 90 top
C1020  SC22U6D3V3MX-1-GP  [C603H40]  71.2 42.42 0 top
C1021  SC180P50V2JN-1DLGP  [C402H22]  74.91 47.45 270 top
C1022  SC22U6D3V3MX-1-DL-GP  [C603H40]  89 53.09 90 top
C1023  SC22U6D3V3MX-1-GP  [C603H40]  89.79 44.43 90 top
C1024  SC22U6D3V3MX-1-DL-GP  [C603H40]  88.37 49.68 90 top
C1025  SC22U6D3V3MX-1-DL-GP  [C603H40]  87.15 61.06 270 top
C1026  SC22U6D3V3MX-1-DL-GP  [C603H40]  88.98 60.78 180 top
C1027  SC22U6D3V3MX-1-DL-GP  [C603H40]  90.02 42.57 0 top
C1028  SC22U6D3V3MX-1-GP  [C603H40]  89.74 46.59 90 top
C1029  SC22U6D3V3MX-1-GP  [C603H40]  90.25 60.78 180 top
C1030  SC22U6D3V3MX-1-GP  [C603H40]  90.58 48.26 90 top
C1031  SC1U10V2KX-1DLGP  [C402H22]  87.93 51.21 90 top
C1032  SC1U10V2KX-1GP  [C402H22]  87.5 43.18 0 top
C1033  SC180P50V2JN-1DLGP  [C402H22]  85.62 53.06 0 top
C1034  SC22U6D3V3MX-1-GP  [C603H40]  79.83 62.18 270 top
C1035  SC22U6D3V3MX-1-DL-GP  [C603H40]  84.94 55.12 90 top
C1036  SC1KP50V2KX-1GP  [C402H22]  80.16 56.77 270 top
C1037  SC10U6D3V3MX-DL-GP  [C603H36]  79.81 60.89 270 top
C1038  SC1KP50V2KX-1GP  [C402H22]  85.45 56.9 90 top
C1039  SC1KP50V2KX-1DLGP  [C402H22]  80.14 55.98 270 top
C1040  SC22U6D3V3MX-1-DL-GP  [C603H40]  82.98 54.74 0 top
C1041  SC22U6D3V3MX-1-GP  [C603H40]  75.41 77.95 90 bottom
C1042  SC180P50V2JN-1DLGP  [C402H22]  79.71 59.21 270 top
C1043  SC22U6D3V3MX-1-GP  [C603H40]  71.27 60.38 180 top
C1044  SC1U10V2KX-1GP  [C402H22]  70.23 60.81 180 top
C1045  SC1U10V2KX-1DLGP  [C402H22]  68.71 58.12 270 top
C1046  SC1KP50V2KX-1DLGP  [C402H22]  85.45 56.14 90 top
C1047  SC10U6D3V3MX-GP  [C603H38]  75.41 79.25 90 bottom
C1048  SC10U6D3V3MX-GP  [C603H38]  73.96 55.37 180 top
C1049  SC1U10V2KX-1DLGP  [C402H22]  76.06 54.3 90 top
C1050  SC1KP50V2KX-1DLGP  [C402H22]  75.19 52.39 0 top
C1051  SC22U6D3V3MX-1-DL-GP  [C603H40]  84.76 61.06 90 top
C1052  SC10U6D3V3MX-DL-GP  [C603H36]  77.27 58.6 90 top
C1053  SC1U10V2KX-1DLGP  [C402H22]  75.39 56.77 270 top
C1054  SC1KP50V2KX-1DLGP  [C402H22]  75.56 57.58 270 top
C1055  SC10U6D3V3MX-DL-GP  [C603H36]  82.75 78.06 270 bottom
C1056  SC1U10V2KX-1DLGP  [C402H22]  76.88 56.42 180 top
C1057  SC1KP50V2KX-1DLGP  [C402H22]  75.9 55.17 270 top
C1058  SC10U6D3V3MX-GP  [C603H38]  77.93 63.68 270 top
C1059  SC1U10V2KX-1DLGP  [C402H22]  77.72 56.44 180 top
C1060  SC1KP50V2KX-1DLGP  [C402H22]  77.77 54.3 270 top
C1061  SC10U6D3V3MX-DL-GP  [C603H36]  78.77 56.77 180 top
C1062  SC1U10V2KX-1DLGP  [C402H22]  79.83 55.17 90 top
C1063  SC1KP50V2KX-1DLGP  [C402H22]  79.83 54.39 90 top
C1064  SC22U6D3V3MX-1-GP  [C603H40]  74.09 60.86 270 top
C1065  SC1U10V2KX-1DLGP  [C402H22]  76.02 60.66 90 top
C1066  SCD22U10V2KX-2-GP  [C402H22]  72.26 58.14 180 top
C1067  SC22U6D3V3MX-1-DL-GP  [C603H40]  83.67 46.91 90 top
C1068  SC22U6D3V3MX-1-DL-GP  [C603H40]  84.32 48.83 90 top
C1069  SC22U6D3V3MX-1-GP  [C603H40]  56.64 48.36 270 bottom
C1070  SC22U6D3V3MX-1-DL-GP  [C603H40]  81.3 46.91 90 top
C1071  SC22U6D3V3MX-1-DL-GP  [C603H40]  76.81 52.69 180 top
C1072  SC22U6D3V3MX-1-GP  [C603H40]  75.92 50.85 270 top
C1073  SC22U6D3V3MX-1-DL-GP  [C603H40]  81.34 52.86 90 top
C1074  SC22U6D3V3MX-1-GP  [C603H40]  78.84 52.71 180 top
C1075  SC1U10V2KX-1DLGP  [C402H22]  71.58 39.07 90 top
C1076  SC1U10V2KX-1DLGP  [C402H22]  72.98 44.89 180 top
C1077  SC1U10V2KX-1GP  [C402H22]  86.41 53.06 0 top
C1078  SC10U6D3V3MX-DL-GP  [C603H36]  59.16 61.88 90 bottom
C1079  SC1KP50V2KX-1GP  [C402H22]  69.44 60.81 180 top
C1080  SC1KP50V2KX-1DLGP  [C402H22]  68.71 58.88 270 top
C1081  SC1KP50V2KX-1DLGP  [C402H22]  76.02 61.42 90 top
C1201  SCD1U16V2KX-3DLGP  [C402H22]  137.39 80.8 180 top
C1202  SC1KP50V2KX-1DLGP  [C402H22]  130.86 63.53 180 top
C1203  SC10U6D3V2MX-2-GP  [C402-TO0D2H28]  121.92 55.02 270 top
C1204  SC10U6D3V2MX-GP-U  [C402-TO0D2H28]  122.05 51.54 270 top
C1205  SC10U6D3V2MX-GP-U  [C402-TO0D2H28]  130.3 52.15 180 top
C1206  SC10U6D3V2MX-2-GP  [C402-TO0D2H28]  130.3 56.34 180 top
C1207  SC10U6D3V2MX-2-GP  [C402-TO0D2H28]  130.18 61.04 0 top
C1208  SC10U6D3V2MX-GP-U  [C402-TO0D2H28]  122.38 62.94 180 top
C1209  SC10U6D3V2MX-GP-U  [C402-TO0D2H28]  124.13 46.66 0 top
C1210  SC10U6D3V2MX-2-GP  [C402-TO0D2H28]  130.43 47.96 0 top
C1211  SC1KP50V2KX-1GP  [C402H22]  129.03 46.18 90 top
C1212  SC1U10V2KX-1GP  [C402H22]  121.82 59.95 270 top
C1213  SC1U10V2KX-1GP  [C402H22]  123.24 46.66 0 top
C1214  SC1U10V2KX-1GP  [C402H22]  130.18 58.75 0 top
C1215  SC1U10V2KX-1DLGP  [C402H22]  121.49 62.89 180 top
C1216  SC1U10V2KX-1DLGP  [C402H22]  130.3 54.43 180 top
C1217  SC1U10V2KX-1DLGP  [C402H22]  121.89 50.62 270 top
C1218  SC1U10V2KX-1DLGP  [C402H22]  121.82 60.73 270 top
C1219  SC1U10V2KX-1GP  [C402H22]  130.3 50.12 180 top
C1220  SCD1U16V2KX-3DLGP  [C402H22]  129.34 63.53 180 top
C1221  SC10U6D3V3MX-DL-GP  [C603H36]  122.5 84.02 0 top
C1222  SC10U6D3V3MX-DL-GP  [C603H36]  132.31 87.33 0 bottom
C1223  SC1U10V2KX-1DLGP  [C402H22]  130.2 85.98 180 top
C1224  SCD1U16V2KX-3DLGP  [C402H22]  130.1 63.53 180 top
C1225  SC10U6D3V3MX-GP  [C603H38]  121.21 84.02 0 top
C1226  SC1U10V2KX-1DLGP  [C402H22]  123.55 84.61 0 top
C1227  SC1U10V2KX-1GP  [C402H22]  122.12 85.7 270 top
C1228  SCD1U16V2KX-3GP  [C402H22]  130.96 85.98 180 top
C1601  SC15P50V2JN-DL-GP  [C402H22]  63.55 42.6 180 bottom
C1602  SC15P50V2JN-DL-GP  [C402H22]  63.5 40.49 0 bottom
C1603  SC6D8P50V2DN-GP  [C402H22]  82.91 71.05 270 bottom
C1701  SC150P50V2KX-GP  [C402H22]  93.6 81.92 0 bottom
C1702  SC1U10V2KX-1GP  [C402H22]  59.79 55.15 0 bottom
C1703  SC18P50V2JN-1DLGP  [C402H22]  64.19 66.37 0 bottom
C1704  SC18P50V2JN-1DLGP  [C402H22]  64.62 62.49 180 bottom
C2401  SC22P50V2JN-4DLGP  [C402H22]  62.56 36.63 270 bottom
C2402  SCD1U16V2KX-3DLGP  [C402H22]  52.88 37.19 180 bottom
C2403  SCD1U16V2KX-3DLGP  [C402H22]  38.43 33.12 180 bottom
C2414  SC10U6D3V3MX-DL-GP  [C603H36]  41.1 25.94 90 bottom
C2416  SC10U6D3V3MX-DL-GP  [C603H36]  45.62 38.46 270 bottom
C2417  SCD1U16V2KX-3GP  [C402H22]  40.59 34.85 180 top
C2428  SCD1U16V2KX-3GP  [C402H22]  40.41 36.73 90 bottom
C2429  SCD1U16V2KX-3DLGP  [C402H22]  53.7 36.65 0 bottom
C2430  SCD1U16V2KX-3DLGP  [C402H22]  61.11 26.98 0 bottom
C2431  SCD1U16V2KX-3DLGP  [C402H22]  60.35 26.98 0 bottom
C2432  SCD1U16V2KX-3DLGP  [C402H22]  60.83 31.35 180 bottom
C2433  SC2D2U10V3KX-1DLGP-U  [C603H36]  61.9 30.91 180 bottom
C2436  SCD1U16V2KX-3DLGP  [C402H22]  40.23 36.02 90 top
C2438  SCD1U16V2KX-3DLGP  [C402H22]  39.27 36.96 180 bottom
C2439  SCD1U16V2KX-3DLGP  [C402H22]  39.9 31.24 90 bottom
C2440  SCD1U16V2KX-3DLGP  [C402H22]  40.87 25.81 270 top
C2441  SCD1U16V2KX-3DLGP  [C402H22]  54.46 36.65 0 bottom
C2442  SCD1U16V2KX-3DLGP  [C402H22]  39.57 23.37 90 top
C2443  SC1U10V2KX-1DLGP  [C402H22]  58.57 22.23 90 top
C2444  SCD1U16V2KX-3DLGP  [C402H22]  50.75 26.6 180 top
C2445  SCD1U16V2KX-3DLGP  [C402H22]  62.56 35.84 270 bottom
C2446  SCD1U16V2KX-3DLGP  [C402H22]  64.95 33.73 270 bottom
C2447  SCD1U16V2KX-3GP  [C402H22]  43.33 33.56 0 top
C2448  SCD1U16V2KX-3DLGP  [C402H22]  40.12 29.78 0 top
C2501  SCD1U16V2KX-3DLGP  [C402H22]  75.36 21.21 90 bottom
C2502  SC10U6D3V3MX-GP  [C603H38]  75.62 19.64 180 bottom
C2507  SC1U10V2KX-1DLGP  [C402H22]  54.43 38.15 180 bottom
C2508  SC1U10V2KX-1DLGP  [C402H22]  58.06 42.67 270 bottom
C2601  SCD1U16V2KX-3DLGP  [C402H22]  90.55 26.24 90 bottom
C2602  SC10U6D3V3MX-DL-GP  [C603H36]  94.26 27.84 0 bottom
C2604  SC470P50V2KX-3GP  [C402H22]  56.72 51.77 90 top
C2605  SC2200P50V2KX-2DLGP  [C402H22]  94.49 22.81 0 bottom
C2606  SCD1U16V2KX-3GP  [C402H22]  38.23 35.36 0 bottom
C2612  SCD1U16V2KX-3DLGP  [C402H22]  45.42 32.21 180 top
C2613  SC100P50V2JN-3DLGP  [C402H22]  41.45 32.97 90 top
C2701  SC10U10V3MX-1-GP  [C603H36]  138.38 77.19 180 top
C2702  SC4D7U6D3V2MX-1-GP  [C402H22]  142.14 93.19 0 top
C2703  SC4D7U6D3V2MX-1-GP  [C402H22]  141.35 94.01 0 top
C2704  SCD1U16V2KX-3DLGP  [C402H22]  141.22 82.12 270 top
C2705  SC2D2U6D3V2MX-DL-GP  [C402H22]  142.04 81.33 270 top
C2706  SCD1U16V2KX-3DLGP  [C402H22]  140.92 95.43 270 top
C2707  SC4D7U6D3V2MX-1-GP  [C402H22]  140.92 96.19 270 top
C2708  SC2D2U10V3KX-1DLGP-U  [C603H36]  142.34 86.95 0 top
C2709  SC2D2U6D3V2MX-DL-GP  [C402H22]  140.89 85.32 0 top
C2710  SC10U6D3V3MX-DL-GP  [C603H36]  143.28 84.05 0 top
C2711  SC10U6D3V3MX-DL-GP  [C603H36]  141.99 84.05 0 top
C2712  SCD1U16V2KX-3DLGP  [C402H22]  139.45 77.17 180 top
C2713  SC10U10V3MX-1-GP  [C603H36]  146.79 84.23 0 top
C2714  SCD1U16V2KX-3DLGP  [C402H22]  145.77 84.66 0 top
C2715  SC10U6D3V3MX-DL-GP  [C603H36]  146.2 96.78 0 top
C2717  SC10U10V3MX-1-GP  [C603H36]  148.06 84.23 0 top
C2718  SCD1U16V2KX-3DLGP  [C402H22]  148.23 88.24 0 bottom
C2720  SC10U6D3V3MX-DL-GP  [C603H36]  151.09 88.81 270 bottom
C2721  SCD1U16V2KX-3DLGP  [C402H22]  149.5 89.33 0 bottom
C2722  SC10U6D3V3MX-DL-GP  [C603H36]  148.46 90.37 180 bottom
C2723  SC10U6D3V3MX-DL-GP  [C603H36]  149 92.2 90 bottom
C2724  SCD1U16V2KX-3DLGP  [C402H22]  148.95 93.22 90 bottom
C2725  SC22P50V2JN-4DLGP  [C402H22]  152.07 88.52 180 top
C2735  SCD1U16V2KX-3DLGP  [C402H22]  152.25 95.38 0 top
C2739  SC100P50V2JN-3DLGP  [C402H22]  153.37 96.01 90 top
C2740  SC2D2U10V3KX-1DLGP-U  [C603H36]  151.09 87.52 270 bottom
C2741  SCD1U16V2KX-3DLGP  [C402H22]  149.68 86.13 180 bottom
C2742  SC2D2U10V3KX-1DLGP-U  [C603H36]  151.79 93.83 0 bottom
C2743  SCD1U16V2KX-3DLGP  [C402H22]  150.11 93.63 0 bottom
C2902  SC10U6D3V3MX-DL-GP  [C603H36]  135.76 98.33 0 bottom
C2907  SC10U6D3V3MX-DL-GP  [C603H36]  142.57 96.67 180 top
C2908  SC10U6D3V3MX-DL-GP  [C603H36]  143.89 96.67 180 top
C3301  SCD1U16V2KX-3DLGP  [C402H22]  8.71 38 0 bottom
C3302  SCD1U16V2KX-3DLGP  [C402H22]  16.59 28.63 90 top
C3303  SCD01U16V2KX-3GP  [C402H22]  16.59 27.87 90 top
C3304  SC4D7U6D3V3KX-DLGP  [C603H36]  16.51 25.38 180 bottom
C3305  SC10U6D3V3MX-GP  [C603H38]  7.67 37.8 0 bottom
C3306  SCD1U16V2KX-3DLGP  [C402H22]  10.44 35.56 180 bottom
C3307  SC4D7U6D3V3KX-DLGP  [C603H36]  11.48 36.04 180 bottom
C3308  SC1U10V2KX-1DLGP  [C402H22]  14.71 37.97 0 bottom
C3309  SC1U10V2KX-1DLGP  [C402H22]  7.8 39.75 270 bottom
C3505  SCD1U16V2KX-3DLGP  [C402H22]  19.3 42.45 0 bottom
C3506  SCD1U16V2KX-3DLGP  [C402H22]  20.07 42.45 0 bottom
C3508  SC1P50V2CN-1GP  [C402H22]  20.09 45.72 270 bottom
C3509  SC1P50V2CN-1GP  [C402H22]  18.59 45.72 90 bottom
C3510  SC1P50V2CN-1GP  [C402H22]  18.11 44.2 270 bottom
C3511  SC1P50V2CN-1GP  [C402H22]  16.59 44.2 90 bottom
C3601  SC22U10V5MX-5-GP  [C805H58]  19.13 57.51 270 bottom
C3602  SC22U10V5MX-5-GP  [C805H58]  19.13 59.39 270 bottom
C3606  SCD1U16V2KX-3DLGP  [C402H22]  20.02 62.97 0 bottom
C3608  SCD1U16V2KX-3DLGP  [C402H22]  17.3 56.75 180 bottom
C3609  SC1U10V2KX-1DLGP  [C402H22]  18.85 60.68 270 bottom
C4001  SC1KP50V2KX-1DLGP  [C402H22]  40.03 26.86 90 top
C4002  SC1KP50V2KX-1DLGP  [C402H22]  38.53 26.75 270 bottom
C4003  SC10U10V3MX-1-GP  [C603H36]  36.6 24.56 90 bottom
C4004  SC10U6D3V3MX-GP  [C603H38]  38.07 30.41 0 bottom
C4005  SC1KP50V2KX-1DLGP  [C402H22]  80.14 79.33 90 top
C4006  SC1KP50V2KX-1DLGP  [C402H22]  78.41 79.78 180 top
C4007  SC10U6D3V3MX-GP  [C603H38]  75.44 76.63 270 bottom
C4008  SC33P50V2JN-3GP  [C402H22]  57.2 64.24 270 bottom
C4009  SC1U10V2KX-1DLGP  [C402H22]  57.2 63.45 270 bottom
C4010  SC10U6D3V3MX-GP  [C603H38]  81.71 79.91 180 bottom
C4011  SC1U10V2KX-1GP  [C402H22]  78.38 83.44 90 bottom
C4012  SCD1U16V2KX-3DLGP  [C402H22]  42.72 14.38 180 bottom
C4013  SC33P50V2JN-3GP  [C402H22]  55.75 67.36 90 bottom
C4014  SC1U10V2KX-1DLGP  [C402H22]  55.75 66.58 90 bottom
C4015  SC33P50V2JN-3GP  [C402H22]  59.54 64.24 90 bottom
C4016  SC4D7U6D3V3KX-GP  [C603H36]  59.16 63.17 90 bottom
C4017  SC33P50V2JN-3GP  [C402H22]  80.09 85.78 270 bottom
C4018  SC1U10V2KX-1DLGP  [C402H22]  79.98 84.28 270 bottom
C4027  SC1U10V2KX-1GP  [C402H22]  87.6 83.47 90 bottom
C4028  SC1U10V2KX-1GP  [C402H22]  33.86 26.34 180 top
C4029  SC1U10V2KX-1GP  [C402H22]  34.14 28.02 270 top
C4030  SC1U10V2KX-1GP  [C402H22]  86.31 80.09 90 bottom
C5501  SCD1U16V2KX-3DLGP  [C402H22]  51.94 81.99 180 bottom
C5502  SC4D7U25V5KX-DL-GP  [C805H54]  45.85 81.87 180 bottom
C5503  SC1KP50V2KX-1DLGP  [C402H22]  48.01 82.15 180 bottom
C5504  SCD1U25V2KX-1-DL-GP  [C402H22]  47.19 82.15 180 bottom
C5505  SCD1U16V2KX-3DLGP  [C402H22]  52.7 81.99 180 bottom
C5506  SCD1U16V2KX-3DLGP  [C402H22]  51.18 81.99 180 bottom
C5507  SCD1U16V2KX-3DLGP  [C402H22]  50.42 81.99 180 bottom
C5508  SCD1U16V2KX-3DLGP  [C402H22]  63.69 84.29 90 bottom
C5509  SC1U10V2KX-1DLGP  [C402H22]  63.69 83.53 270 bottom
C5510  SCD1U16V2KX-3DLGP  [C402H22]  49.66 81.99 180 bottom
C5511  SC4D7U6D3V3KX-DLGP  [C603H36]  62.3 82.87 0 bottom
C5512  SC4D7U6D3V3KX-DLGP  [C603H36]  70.84 80.27 0 bottom
C5513  SCD1U16V2KX-3DLGP  [C402H22]  48.9 81.99 180 bottom
C5514  SC4D7U6D3V3KX-DLGP  [C603H36]  69.6 82.4 270 bottom
C5518  SC10P50V2JN-4GP  [C402H22]  60.41 83.27 90 top
C5519  SC4D7U25V5KX-DL-GP  [C805H54]  66.88 81.87 270 bottom
C5520  SCD1U50V3KX-DL-GP  [C603H35]  66.6 83.49 270 bottom
C5521  SC4D7U6D3V3KX-DLGP  [C603H36]  62.15 83.04 180 top
C5701  SCD1U16V2KX-3DLGP  [C402H22]  18.65 84.96 270 top
C5702  SCD1U16V2KX-3DLGP  [C402H22]  18.65 84.15 270 top
C5703  SCD1U16V2KX-3DLGP  [C402H22]  18.62 83.31 270 top
C5704  SCD1U16V2KX-3DLGP  [C402H22]  18.62 82.49 270 top
C5705  SCD1U16V2KX-3DLGP  [C402H22]  18.71 81.68 270 top
C5706  SCD1U16V2KX-3DLGP  [C402H22]  18.71 80.79 270 top
C5707  SCD1U16V2KX-3DLGP  [C402H22]  18.71 79.9 270 top
C5708  SCD1U16V2KX-3DLGP  [C402H22]  18.71 79.01 270 top
C6001  SCD01U50V2KX-1DLGP  [C402H22]  145.9 41.45 270 bottom
C6002  SCD01U50V2KX-1DLGP  [C402H22]  145.9 42.22 270 bottom
C6003  SCD01U50V2KX-1DLGP  [C402H22]  145.92 43.51 270 bottom
C6004  SCD01U50V2KX-1DLGP  [C402H22]  145.92 44.4 270 bottom
C6005  SC10U10V5KX-2DLGP  [C805H50]  145.03 27.28 0 bottom
C6006  SCD1U16V2KX-3DLGP  [C402H22]  144.91 22.1 0 bottom
C6007  SCD01U50V2KX-1DLGP  [C402H22]  140.28 62.79 90 bottom
C6008  SCD01U50V2KX-1DLGP  [C402H22]  140.28 61.98 90 bottom
C6009  SCD01U50V2KX-1DLGP  [C402H22]  141.55 57.99 270 bottom
C6010  SCD01U50V2KX-1DLGP  [C402H22]  141.55 58.78 270 bottom
C6011  SC1U6D3V2KX-DLGP  [C402H22]  150.37 55.37 270 bottom
C6012  SC1U6D3V2KX-DLGP  [C402H22]  144.25 57.18 0 bottom
C6013  SC1U6D3V2KX-DLGP  [C402H22]  143.48 57.18 0 bottom
C6014  SC4D7U6D3V3KX-DLGP  [C603H36]  144.86 31.7 90 bottom
C6015  SC4D7U6D3V3KX-DLGP  [C603H36]  144.86 33.05 90 bottom
C6016  SCD1U16V2KX-3GP  [C402H22]  143.54 41.12 90 bottom
C6017  SC10U10V5KX-2GP  [C805H54]  143.28 38.94 90 bottom
C6018  SCD1U16V2KX-3DLGP  [C402H22]  145.34 30.28 180 bottom
C6019  SCD01U50V2KX-1DLGP  [C402H22]  141.51 58.79 90 top
C6020  SCD01U50V2KX-1DLGP  [C402H22]  141.51 58 90 top
C6021  SCD01U50V2KX-1DLGP  [C402H22]  140.28 62.79 90 top
C6022  SCD01U50V2KX-1DLGP  [C402H22]  140.28 61.98 90 top
C6102  SCD1U16V2KX-3DLGP  [C402H22]  165.68 95.43 180 top
C6103  SC10U6D3V3MX-DL-GP  [C603H36]  151.59 75.52 0 bottom
C6104  SCD1U16V2KX-3DLGP  [C402H22]  164.92 95.43 180 top
C6301  SCD1U16V2KX-3DLGP  [C402H22]  79.76 89.82 0 top
C6302  SC4D7U6D3V2MX-1-GP  [C402H22]  86.15 85.75 180 bottom
C6303  SCD1U16V2KX-3DLGP  [C402H22]  86.13 83.47 270 bottom
C6304  SC4D7U6D3V2MX-1-GP  [C402H22]  85.41 90.45 0 bottom
C6305  SCD1U16V2KX-3DLGP  [C402H22]  85.85 87.59 270 bottom
C6306  SCD1U16V2KX-3DLGP  [C402H22]  41.83 93.68 180 top
C6307  SC10U6D3V3MX-DL-GP  [C603H36]  40.59 93.96 0 bottom
C6308  SC10U6D3V3MX-DL-GP  [C603H36]  54.84 85.02 0 top
C6309  SCD1U16V2KX-3DLGP  [C402H22]  58.83 85.24 0 top
C6310  SC10U6D3V3MX-DL-GP  [C603H36]  57.76 85.8 0 top
C6311  SCD1U16V2KX-3DLGP  [C402H22]  40.94 93.68 180 top
C6312  SCD1U16V2KX-3DLGP  [C402H22]  39.29 93.68 180 top
C6313  SC10U6D3V3MX-DL-GP  [C603H36]  41.91 93.96 0 bottom
C6314  SC10U6D3V3MX-DL-GP  [C603H36]  59.41 91.16 90 top
C6315  SCD1U16V2KX-3DLGP  [C402H22]  50.98 85.15 0 top
C6318  SC10U6D3V3MX-DL-GP  [C603H36]  60.73 85.29 0 top
C6320  SCD1U16V2KX-3DLGP  [C402H22]  51.33 93.73 270 top
C6327  SCD1U16V2KX-3DLGP  [C402H22]  51.77 85.15 0 top
C6330  SCD1U16V2KX-3DLGP  [C402H22]  50.9 94.62 270 top
C6335  SC10U6D3V3MX-DL-GP  [C603H36]  56.13 85.63 0 top
C6337  SCD1U16V2KX-3DLGP  [C402H22]  40.06 93.68 180 top
C6340  SC10U6D3V3MX-DL-GP  [C603H36]  39.32 93.96 0 bottom
C6341  SCD1U16V2KX-3DLGP  [C402H22]  53.59 85.45 0 top
C6343  SC18P50V2JN-1DLGP  [C402H22]  46.46 93.73 180 top
C6344  SC18P50V2JN-1DLGP  [C402H22]  46.46 91.8 0 top
C6345  SCD01U50V2KX-1DLGP  [C402H22]  48.84 94.24 0 top
C6346  SCD01U50V2KX-1DLGP  [C402H22]  48.08 94.24 0 top
C6347  SCD01U50V2KX-1DLGP  [C402H22]  49.38 92.74 0 top
C6348  SCD01U50V2KX-1DLGP  [C402H22]  50.14 92.74 0 top
C6349  SCD1U16V2KX-3DLGP  [C402H22]  84.73 86.59 180 bottom
C6504  SCD1U16V2KX-3DLGP  [C402H22]  43.69 9.5 90 bottom
C6505  SCD1U16V2KX-3DLGP  [C402H22]  46.18 6.74 270 bottom
C6701  SCD047U16V2KX-1-GP  [C402H22]  8.81 42.75 270 top
C6702  SCD1U16V2KX-3DLGP  [C402H22]  7.47 43.92 180 top
C6801  SCD01U50V2KX-1DLGP  [C402H22]  85.85 16.94 270 top
C6901  SC10U6D3V3MX-DL-GP  [C603H36]  93.45 84.33 270 top
C6902  SCD1U16V2KX-3DLGP  [C402H22]  94.06 83.29 270 top
CPU1  2D3201AJN23AC-GP  [BGA769M24D5H67]  79.4 50.32 0 bottom
D2402  RB551V30-GP  [SOD323AKH38]  63.78 27.69 180 bottom
D2403  RB551V30-GP  [SOD323AKH38]  61.61 20.43 270 bottom
D2703  BAT54C-12-GP  [SOT-23-9H44]  150.36 96.56 180 bottom
D2901  BAT54AW-4-GP  [SC70-2D2-312H44]  140.87 92 270 top
D4001  BAT54C-12-GP  [SOT-23-9H44]  29.46 35.59 90 bottom
D4002  RB751VM-40TE-17-GP  [SOD323-2513AKH36]  49.21 10.26 270 bottom
D4003  RB551V30-GP  [SOD323AKH38]  48.63 13.81 0 bottom
D4004  BAT54C-12-GP  [SOT-23-9H44]  89.6 84.81 270 bottom
D4301  LBAV99LT1G-1-GP  [SOT23-2D4-312H44]  94.59 15.93 90 bottom
D4302  LBAV99LT1G-1-GP  [SOT23-2D4-312H44]  100.41 15.83 90 bottom
D4303  LBAV99LT1G-1-GP  [SOT23-2D4-312H44]  97.13 15.93 90 bottom
D5501  BAT54C-7-F-3-GP  [SOT23-2D4-312H48]  68.68 76.89 270 bottom
D5502  BAT54C-12-GP  [SOT-23-9H44]  55.83 78.74 270 bottom
D5701  LBAW56LT1G-GP  [SOT23-2D4-312H44]  16.87 79 90 bottom
DB1  PAD-ACES-CON10-14-GP  [PAD-87212-1002N]  48.69 37.16 0 top
DCIN1  ACES-CON6-20-GP-U  [50224-0060N-W01]  23 81 0 bottom
DIMM1  DDR4-260P-79-GP-U  [40-42271-26001RHF-WD-U]  126 53.5 90 bottom
EC1601  SC22P50V2JN-4GP  [C402H22]  82.93 70.23 270 bottom
EC1701  SC10P50V2JN-4GP  [C402H22]  71.24 52.63 270 top
EC2401  SC100P50V2JN-3GP  [C402H22]  58.87 26.45 0 top
EC2403  AZ5725-01FDR7G-GP  [SOD882-10D6-1H20]  31.52 36.1 0 bottom
EC2601  SC33P50V2JN-3DLGP  [C402H22]  90.91 19 90 bottom
EC2602  SC33P50V2JN-3DLGP  [C402H22]  90.88 17.71 180 bottom
EC2701  SCD1U25V2KX-1-DL-GP  [C402H22]  134.01 98.12 270 top
EC2702  SCD1U25V2KX-1-DL-GP  [C402H22]  136.09 92.53 270 top
EC2703  SCD1U25V2KX-1-DL-GP  [C402H22]  139.27 81.31 270 top
EC2704  SCD1U25V2KX-1-DL-GP  [C402H22]  143.74 82.25 90 top
EC2705  SCD1U25V2KX-1-DL-GP  [C402H22]  151.05 98.45 90 top
EC2709  SC22P50V2JN-4DLGP  [C402H22]  151.89 90.81 180 top
EC2710  SC22P50V2JN-4DLGP  [C402H22]  150.5 90.4 90 top
EC2711  SC22P50V2JN-4DLGP  [C402H22]  153.77 86.46 0 top
EC2901  SC1KP50V2KX-1DLGP  [C402H22]  90.81 100.74 0 bottom
EC2902  SC1KP50V2KX-1DLGP  [C402H22]  91.44 98.3 180 bottom
EC2903  SC1KP50V2KX-1DLGP  [C402H22]  90.65 97.41 0 bottom
EC2904  SC1KP50V2KX-1DLGP  [C402H22]  90.7 94.87 180 bottom
EC2905  SC100P50V2JN-3DLGP  [C402H22]  149.86 97.44 180 top
EC2906  SC100P50V2JN-3DLGP  [C402H22]  147.02 95.15 270 top
EC2907  SC100P50V2JN-3DLGP  [C402H22]  138.86 88.01 0 top
EC2908  SC100P50V2JN-3DLGP  [C402H22]  138.3 85.57 0 top
EC3301  SC1KP50V2KX-1DLGP  [C402H22]  11.63 43.83 0 top
EC3307  SC6D8P50V2DN-GP  [C402H22]  14.5 44.2 270 bottom
EC4301  SC10P50V2JN-4DLGP  [C402H22]  109.86 16.71 270 top
EC4302  SC10P50V2JN-4DLGP  [C402H22]  109.88 15.62 270 top
EC4303  SCD1U25V2KX-1-DL-GP  [C402H22]  121.82 15.18 90 bottom
EC4304  SCD1U25V2KX-1-DL-GP  [C402H22]  26.54 75.59 270 bottom
EC4305  SC10P50V2JN-4DLGP  [C402H22]  109.98 14.81 90 top
EC4306  SCD1U25V2KX-1-DL-GP  [C402H22]  26.56 74.79 270 bottom
EC4307  SC10P50V2JN-4GP  [C402H22]  20.4 75.47 0 bottom
EC4308  SC1KP50V2KX-1DLGP  [C402H22]  21.87 72.42 270 top
EC4309  SC1KP50V2KX-1DLGP  [C402H22]  21.87 70.82 270 top
EC4310  SC1KP50V2KX-1DLGP  [C402H22]  21.87 70.05 270 top
EC4311  SC1KP50V2KX-1DLGP  [C402H22]  25.91 71.58 90 top
EC4312  SC1KP50V2KX-1DLGP  [C402H22]  25.91 70.82 90 top
EC4313  SC1KP50V2KX-1DLGP  [C402H22]  21.87 71.58 270 top
EC4314  SCD1U25V2KX-1-DL-GP  [C402H22]  20.9 64.16 90 bottom
EC4315  SCD1U25V2KX-1-DL-GP  [C402H22]  21.13 63.35 90 bottom
EC4401  SC10P50V2JN-4GP  [C402H22]  21.13 62.56 270 bottom
EC5501  SCD1U25V2KX-1-DL-GP  [C402H22]  37.69 81.26 90 bottom
EC5502  SCD1U25V2KX-1-DL-GP  [C402H22]  37.69 82.15 90 bottom
EC5503  SCD1U25V2KX-1-DL-GP  [C402H22]  37.69 82.91 90 bottom
EC5505  SC22P50V2JN-4DLGP  [C402H22]  55.55 80.72 90 top
EC5506  SC22P50V2JN-4DLGP  [C402H22]  54.05 80.72 270 top
EC5507  SC6P50V2CN-1-NL-GP  [C402H22]  57.96 82.48 0 top
EC5510  SC33P50V2JN-3DLGP  [C402H22]  68.53 83.75 90 bottom
EC5701  SCD1U25V2KX-1-DL-GP  [C402H22]  12.82 85.68 0 bottom
EC6001  SCD1U16V2KX-3DLGP  [C402H22]  145.67 22.1 180 bottom
EC6002  SC22P50V2JN-4DLGP  [C402H22]  145.28 18.04 270 bottom
EC6501  SC4D7P50V2BN-2-GP  [C402H22]  26.16 11.48 270 bottom
EC6502  SC100P50V2JN-3DLGP  [C402H22]  28.59 5.6 180 bottom
EC6503  SC4D7P50V2BN-2-GP  [C402H22]  26.08 9.13 270 bottom
EC6506  SC1KP50V2KX-1DLGP  [C402H22]  71.45 20.83 0 bottom
EC6601  SC1KP50V2KX-1DLGP  [C402H22]  134.8 86.92 90 bottom
EC6602  SC1KP50V2KX-1GP  [C402H22]  134.82 88.01 90 bottom
EC6603  SC1KP50V2KX-1GP  [C402H22]  134.85 88.88 90 bottom
EC8901  SCD1U25V2KX-1-DL-GP  [C402H22]  36.58 23.06 270 bottom
EC8902  SCD1U25V2KX-1-DL-GP  [C402H22]  13.63 73.37 0 top
EC8903  SCD1U25V2KX-1-DL-GP  [C402H22]  18.67 85.8 270 top
EC8904  SCD1U25V2KX-1-DL-GP  [C402H22]  38.99 29.41 90 top
EC8905  SCD1U25V2KX-1-DL-GP  [C402H22]  58.41 24.47 180 top
ED501  AZ5125-01H-R7G-GP  [SOD-523-4H28]  87.38 39.98 0 top
ED3301  AZ5125-02S-R7G-GP  [SOT23-2D4-312H46]  16.81 36.88 0 bottom
ED3302  AZ5125-02S-R7G-GP  [SOT23-2D4-312H46]  16.13 40.82 180 bottom
ED3303  AZ5125-02S-R7G-GP  [SOT23-2D4-312H46]  8.76 43.44 0 bottom
ED3501  AZ5B25-01F-GP  [D0201H13]  19.94 46.41 270 bottom
ED3502  AZ5B25-01F-GP  [D0201H13]  18.87 46.41 90 bottom
ED3503  AZ5B25-01F-GP  [D0201H13]  17.96 44.91 270 bottom
ED3504  AZ5B25-01F-GP  [D0201H13]  16.87 44.91 90 bottom
ED3505  AZC099-04S-2-GP  [SOT-6H58]  18.06 50.75 0 bottom
ED5501  AZC099-04S-2-GP  [SOT-6H58]  59.79 81.79 180 bottom
ED6001  AZ1043-04F-R7G-GP  [DFN10G2510H22]  145.24 47.04 180 bottom
ED6002  AZ1043-04F-R7G-GP  [DFN10G2510H22]  145.24 47.04 180 top
EL3301  FILTER-4P-156-GP-U  [L125100-4PH24]  14.07 35.56 90 bottom
EL3503  FILTER-4P-156-GP-U  [L125100-4PH24]  20.55 50.04 180 bottom
EL4301  -  [0R0402-PAD]  24.66 72.93 0 top
EL4302  -  [0R0402-PAD]  23.88 72.93 0 top
EL4303  -  [0R0402-PAD]  23.01 72.94 0 top
EL4304  -  [0R0402-PAD]  25.48 72.93 0 top
EL5501  FILTER-4P-156-GP-U  [L125100-4PH24]  53.98 82.02 0 bottom
EL5502  FILTER-4P-156-GP-U  [L125100-4PH24]  60.43 79 0 bottom
EL6101  FILTER-4P-156-GP-U  [L125100-4PH24]  148.83 100.66 270 bottom
EL6602  FILTER-4P-156-GP-U  [L125100-4PH24]  135.05 77.78 0 bottom
EL6603  FILTER-4P-156-GP-U  [L125100-4PH24]  132.72 79.76 0 bottom
EL6604  FILTER-4P-156-GP-U  [L125100-4PH24]  132.61 83.64 0 bottom
ER5714  150R2F-1-GP  [R402H16]  17.36 82.88 0 top
ER5715  150R2F-1-GP  [R402H16]  17.36 81.2 0 top
ER5716  150R2F-1-GP  [R402H16]  17.35 79.47 0 top
ER5717  150R2F-1-GP  [R402H16]  17.38 84.69 0 top
F5501  POLYSW-1D1A24V-GP-U  [POLYSW-4633-UH43]  42.01 82.22 270 bottom
F5502  POLYSW-1D1A6V-9-GP-U  [POLYSW-2114H30]  69.27 80.04 0 bottom
F5503  POLYSW-1D1A6V-9-GP-U  [POLYSW-2114H30]  65.89 79.45 0 bottom
F5701  POLYSW-1D1A6V-9-GP-U  [POLYSW-2114H30]  14.66 85.4 270 bottom
FC1001  SC18P50V2JN-1DLGP  [C402H22]  59.09 63.5 270 top
FC1002  SC18P50V2JN-1DLGP  [C402H22]  13.71 71.37 180 top
FC1003  SC18P50V2JN-1DLGP  [C402H22]  13.06 75.28 270 top
FC1201  SC18P50V2JN-1DLGP  [C402H22]  121.9 49.86 270 top
FC1202  SC18P50V2JN-1DLGP  [C402H22]  91.05 42.81 0 top
FC1601  SC8P50V2DN-1DL-GP  [C402H22]  45.42 33.34 270 top
FC2401  SC18P50V2JN-1DLGP  [C402H22]  50.58 24.68 90 top
FC6002  SC18P50V2JN-1DLGP  [C402H22]  143.54 40.31 90 bottom
FC8901  SC18P50V2JN-1DLGP  [C402H22]  43.48 68.25 270 bottom
FC8902  SC18P50V2JN-1DLGP  [C402H22]  31.45 61.95 270 bottom
FC8903  SC18P50V2JN-1DLGP  [C402H22]  21.49 31.14 270 bottom
FC8904  SC18P50V2JN-1DLGP  [C402H22]  143.48 54 180 top
FC8905  SC18P50V2JN-1DLGP  [C402H22]  143.66 20.3 90 top
FC8906  SC18P50V2JN-1DLGP  [C402H22]  44.6 11.33 180 top
FC8907  SC18P50V2JN-1DLGP  [C402H22]  17.58 6.05 270 top
FC8908  SC18P50V2JN-1DLGP  [C402H22]  17.6 16.38 270 top
FC8909  SC18P50V2JN-1DLGP  [C402H22]  27.25 31.65 90 top
FC8910  SC18P50V2JN-1DLGP  [C402H22]  15.9 44.25 270 top
FC8911  SC18P50V2JN-1DLGP  [C402H22]  22.3 59.74 90 top
FC8912  SC18P50V2JN-1DLGP  [C402H22]  15.88 65.56 270 top
FC8913  SC18P50V2JN-1DLGP  [C402H22]  30.23 74.45 90 top
FC8914  SC18P50V2JN-1DLGP  [C402H22]  33.4 62.87 0 top
FC8915  SC18P50V2JN-1DLGP  [C402H22]  28.98 80.34 270 top
FC8916  SC18P50V2JN-1DLGP  [C402H22]  67.44 83.49 90 top
FC8917  SC18P50V2JN-1DLGP  [C402H22]  99.77 94.29 180 top
FC8918  SC18P50V2JN-1DLGP  [C402H22]  129.77 76.4 270 top
FC8919  SC18P50V2JN-1DLGP  [C402H22]  145.57 19.18 270 top
FC8920  SC18P50V2JN-1DLGP  [C402H22]  136.02 3.3 0 top
FC8921  SC18P50V2JN-1DLGP  [C402H22]  142.14 72.93 90 top
FC8922  SC18P50V2JN-1DLGP  [C402H22]  73.33 27.64 0 bottom
FC8923  SC18P50V2JN-1DLGP  [C402H22]  74.12 99.44 180 top
FC8924  SC18P50V2JN-1DLGP  [C402H22]  104.29 98.58 0 top
FC8925  SC18P50V2JN-1DLGP  [C402H22]  119.61 98.6 0 top
FC8926  SC18P50V2JN-1DLGP  [C402H22]  79.71 58.37 270 top
FC8927  SC18P50V2JN-1DLGP  [C402H22]  74.85 78.92 180 top
G1701  GAP-OPEN  [CON2O-U]  62.61 54.94 0 bottom
G1702  GAP-OPEN  [CON2O-U]  64.14 54.94 0 bottom
H1  HOLE354R237-GP  [HOLE354R237]  10.3 4.65 180 bottom
H4  HOLE335R197-GP  [HOLE335R197]  74.5 87.85 180 bottom
H9  HOLE335R197-GP  [HOLE335R197]  69.3 3.05 180 bottom
H10  HOLE276R178-GP  [HOLE276R178]  89.85 69.72 180 bottom
H11  HOLE276R178-GP  [HOLE276R178]  89.85 30.92 180 bottom
H12  HOLE276R178-GP  [HOLE276R178]  68.95 30.92 180 bottom
H13  HOLE276R178-GP  [HOLE276R178]  68.95 69.72 180 bottom
H14  HOLE335R142-GP  [HOLE335R142]  142.7 4.65 0 top
HDA27  ALC3204-CG-GP-U  [QFN40J5-G3D75H36]  145.92 90.37 270 top
HDD1  SKT-SATA7P-15P-193-GP  [15-02330-3A03-A]  150 30.85 270 bottom
HDMI1  SKT-HDMI23-147-GP-U  [SKT-HDMI23-188125-5]  2.7 77 90 bottom
HDT1  DM-SMC-CONN20A-1-GP-01  [DM-ASP-137098-05-01]  88.39 21.54 0 top
IOBD1  ACES-CON44-2-GP  [132F44-000000-A2-R]  140.6 86.8 270 bottom
KB1  ACES-CON30-29-GP  [50699-03001-W01]  91 9.8 180 bottom
LCD1  ACES-CON40-18-GP  [51540-04001-W01]  55.85 88.4 0 bottom
LIDSW1  S-5712ACDL1-M3T1U-GP  [SOT23-2D8-123H52]  3.9 38 180 top
NOREF  *  [unnamed]  29.72 30.74 0 top
NOREF#2  -  [#2]  116.75 29.77 0 top
NOREF#3  -  [unnamed]  154.19 4.17 0 top
NOREF#4  *  [unnamed]  150.69 1.28 0 top
NOREF#5  *  [unnamed]  132.96 95.28 0 top
NOREF#6  -  [unnamed]  32.56 209.17 0 top
NOREF#7  *  [unnamed]  35.81 58.84 0 top
NOREF#8  -  [unnamed]  98.88 -1.68 0 top
NOREF#9  -  [#2]  0 11 0 top
NOREF#10  -  [unnamed]  21.06 96.52 0 top
NOREF#11  -  [unnamed]  168.51 111.35 0 top
NOREF#12  -  [#2]  0 11 0 top
NOREF#13  -  [#2]  5.21 10.01 0 top
NOREF#14  -  [#2]  18.39 1.7 0 top
NOREF#15  -  [#2]  178.16 13.48 180 top
NOREF#16  -  [#2]  78.23 -6.9 0 top
NOREF#17  *  [unnamed]  76.16 94.95 0 top
NOREF#18  -  [unnamed]  3 3 0 top
NOREF#19  -  [#2]  0 11 0 top
NOREF#20  *  [unnamed]  108.51 95.8 0 top
NOREF#21  *  [unnamed]  27.45 207.32 0 top
NOREF#22  -  [#2]  171.07 83.77 0 top
NOREF#23  -  [unnamed]  15.52 96.65 0 top
NOREF#24  -  [#2]  0 11 0 top
NOREF#25  *  [unnamed]  167.46 98.3 0 top
NOREF#26  -  [#2]  0 11 0 top
NOREF#27  *  [unnamed]  143.89 17.16 0 top
NOREF#28  *  [unnamed]  177.73 209.61 0 top
NOREF#29  *  [unnamed]  51.59 7.51 0 top
NOREF#30  *  [unnamed]  62.08 94.6 0 top
NOREF#31  -  [unnamed]  85.15 209.68 0 top
NOREF#32  -  [#2]  165.64 206.3 180 top
NOREF#33  *  [unnamed]  93.12 76.65 0 top
NOREF#34  -  [#2]  57.48 212.4 0 top
NOREF#35  *  [unnamed]  4.72 13.84 0 top
NOREF#36  -  [#2]  -1702.86 -447.47 0 top
NOREF#37  -  [unnamed]  162.97 111.48 0 top
NOREF#38  *  [unnamed]  74.42 35.56 0 top
NOREF#39  -  [#2]  5.87 194.52 0 top
NOREF#40  *  [unnamed]  47.1 84.34 0 top
NOREF#41  -  [unnamed]  175.28 212.31 0 top
NOREF#42  -  [unnamed]  6.49 -4.09 0 top
NOREF#43  -  [unnamed]  152.22 -2.61 0 top
NOREF#44  -  [unnamed]  29.84 203.83 0 top
NOREF#45  -  [#2]  171.86 87.68 180 bottom
NOREF#46  -  [#2]  106.86 29.62 180 bottom
NOREF#47  *  [unnamed]  177.73 209.61 180 bottom
NOREF#48  *  [unnamed]  4.04 65.1 180 bottom
NOREF#49  -  [#2]  2.92 6.22 180 bottom
NOREF#50  *  [unnamed]  98.31 87.24 180 bottom
NOREF#51  *  [unnamed]  51.55 7.25 180 bottom
NOREF#52  *  [unnamed]  27.45 207.32 180 bottom
NOREF#53  *  [unnamed]  69.74 92.98 180 bottom
NOREF#54  *  [unnamed]  95.4 34.43 180 bottom
NOREF#55  -  [#2]  58.5 5.44 180 bottom
NOREF#56  -  [#2]  74.38 212.39 180 bottom
